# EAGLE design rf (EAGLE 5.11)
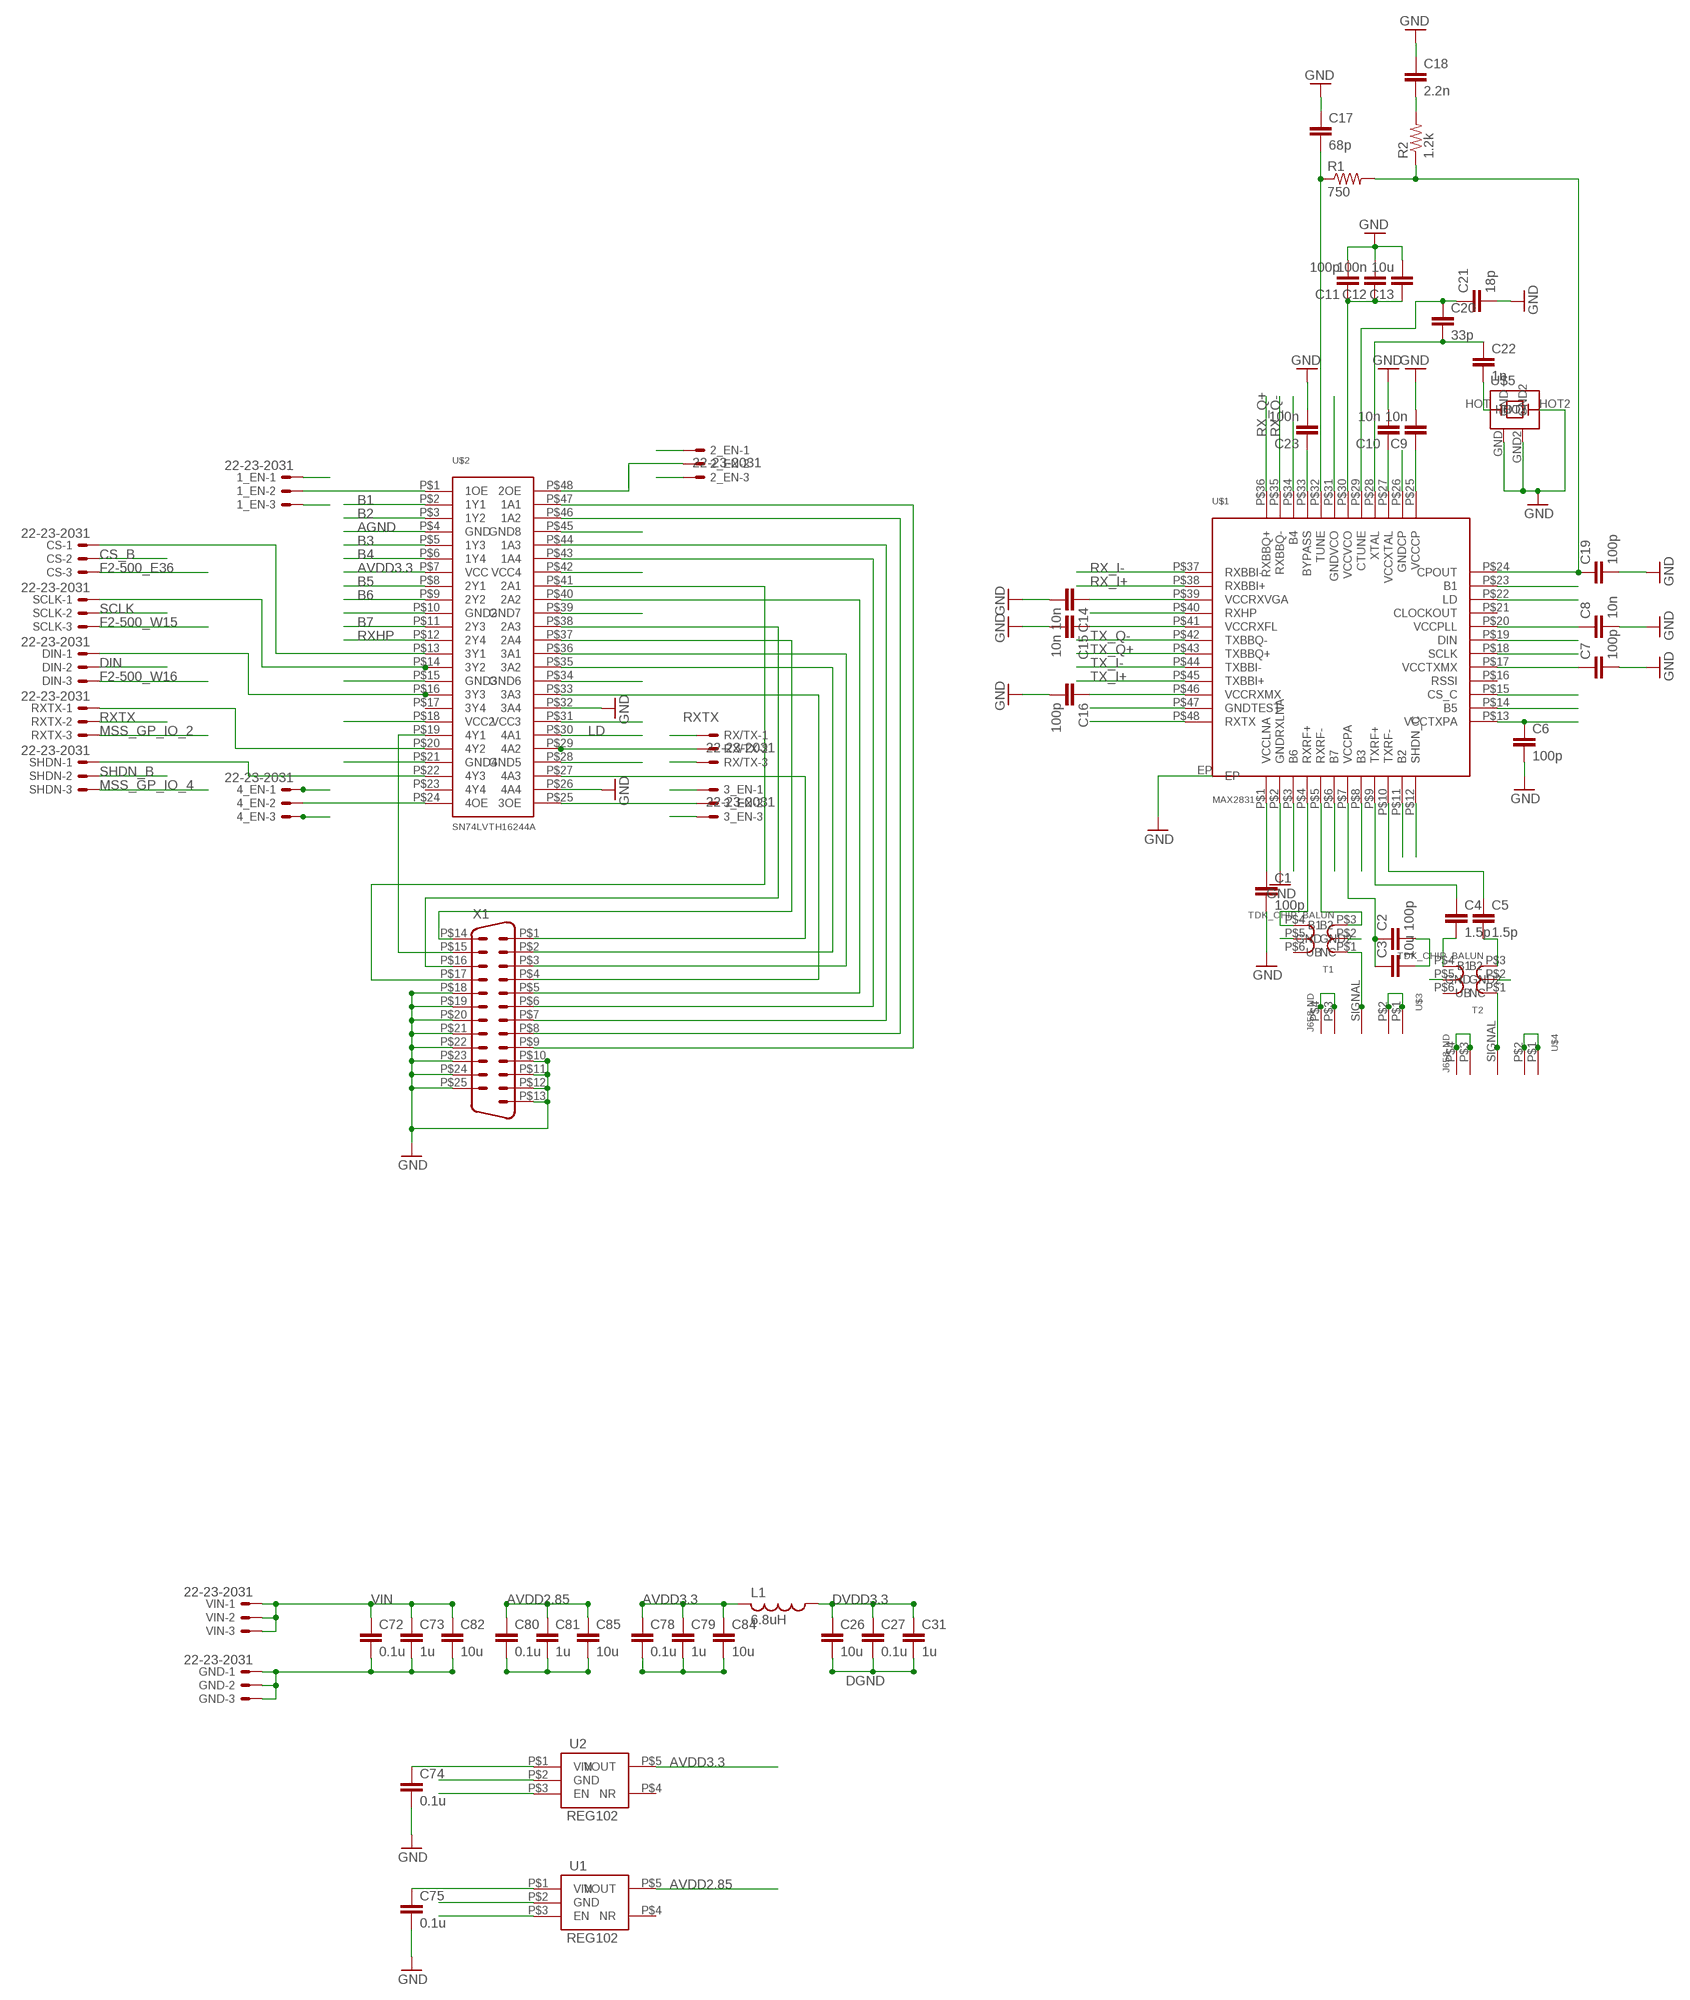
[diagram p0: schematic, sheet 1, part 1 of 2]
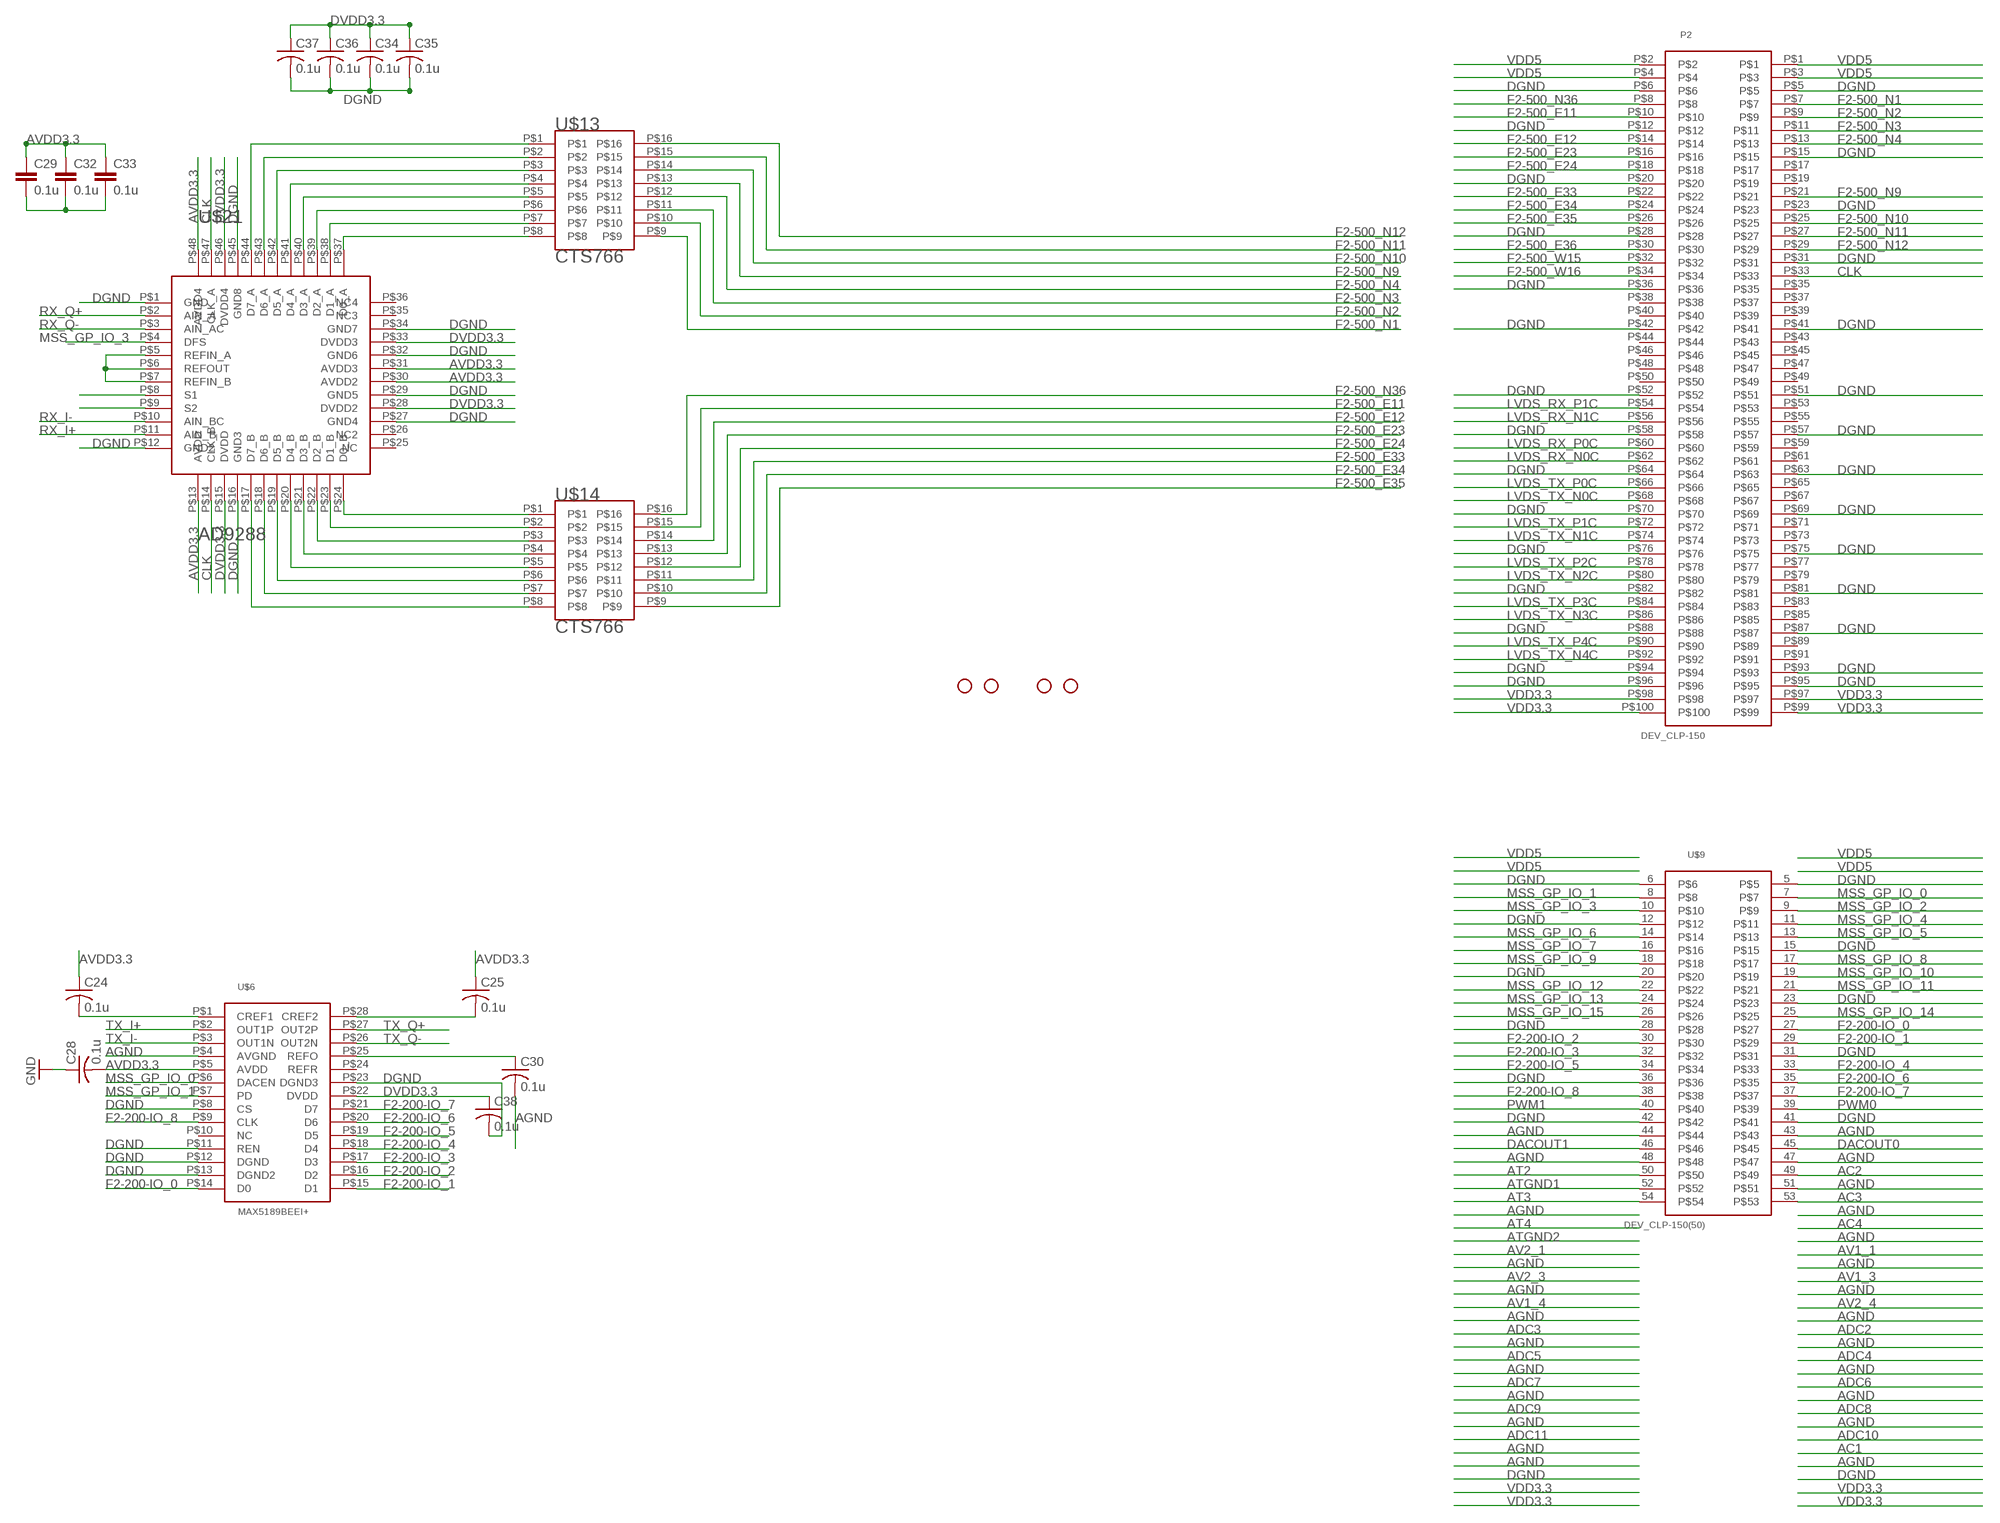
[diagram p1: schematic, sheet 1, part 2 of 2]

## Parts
1_EN  22-23-2031  [22-23-2031]
2_EN  22-23-2031  [22-23-2031]
3_EN  22-23-2031  [22-23-2031]
4_EN  22-23-2031  [22-23-2031]
C1  100p  CAP0402-CAP  [0402-CAP]
C2  100p  CAP0402-CAP  [0402-CAP]
C3  10u  CAP0805  [0805]
C4  1.5p  CAP0402-CAP  [0402-CAP]
C5  1.5p  CAP0402-CAP  [0402-CAP]
C6  100p  CAP0402-CAP  [0402-CAP]
C7  100p  CAP0402-CAP  [0402-CAP]
C8  10n  CAP0402-CAP  [0402-CAP]
C9  10n  CAP0402-CAP  [0402-CAP]
C10  10n  CAP0402-CAP  [0402-CAP]
C11  100p  CAP0402-CAP  [0402-CAP]
C12  100n  CAP0402-CAP  [0402-CAP]
C13  10u  CAP0805  [0805]
C14  10n  CAP0402-CAP  [0402-CAP]
C15  10n  CAP0402-CAP  [0402-CAP]
C16  100p  CAP0402-CAP  [0402-CAP]
C17  68p  CAP0402-CAP  [0402-CAP]
C18  2.2n  CAP0402-CAP  [0402-CAP]
C19  100p  CAP0402-CAP  [0402-CAP]
C20  33p  CAP0402-CAP  [0402-CAP]
C21  18p  CAP0402-CAP  [0402-CAP]
C22  1n  CAP0402-CAP  [0402-CAP]
C23  100n  CAP0402-CAP  [0402-CAP]
C24  0.1u  C-USC0603  [C0603]
C25  0.1u  C-USC0603  [C0603]
C26  10u  CAP0805  [0805]
C27  0.1u  CAP0603-CAP  [0603-CAP]
C28  0.1u  C-USC0603  [C0603]
C29  0.1u  CAP0603-CAP  [0603-CAP]
C30  0.1u  C-USC0603  [C0603]
C31  1u  CAP0603-CAP  [0603-CAP]
C32  0.1u  CAP0603-CAP  [0603-CAP]
C33  0.1u  CAP0603-CAP  [0603-CAP]
C34  0.1u  C-USC0603  [C0603]
C35  0.1u  C-USC0603  [C0603]
C36  0.1u  C-USC0603  [C0603]
C37  0.1u  C-USC0603  [C0603]
C38  0.1u  C-USC0603  [C0603]
C72  0.1u  CAP0603-CAP  [0603-CAP]
C73  1u  CAP0603-CAP  [0603-CAP]
C74  0.1u  CAP0603-CAP  [0603-CAP]
C75  0.1u  CAP0603-CAP  [0603-CAP]
C78  0.1u  CAP0603-CAP  [0603-CAP]
C79  1u  CAP0603-CAP  [0603-CAP]
C80  0.1u  CAP0603-CAP  [0603-CAP]
C81  1u  CAP0603-CAP  [0603-CAP]
C82  10u  CAP0805  [0805]
C84  10u  CAP0805  [0805]
C85  10u  CAP0805  [0805]
CS  22-23-2031  [22-23-2031]
DIN  22-23-2031  [22-23-2031]
GND  22-23-2031  [22-23-2031]
JP4  STAND-OFF  [STAND-OFF]
JP5  STAND-OFF  [STAND-OFF]
JP6  STAND-OFF  [STAND-OFF]
JP7  STAND-OFF  [STAND-OFF]
L1  6.8uH  L-US  [L1210]
P2  DEV_CLP-150  [CLP-150]
R1  750  RESISTOR0402-RES  [0402-RES]
R2  1.2k  RESISTOR0402-RES  [0402-RES]
RX/TX  22-23-2031  [22-23-2031]
RXTX  22-23-2031  [22-23-2031]
SCLK  22-23-2031  [22-23-2031]
SHDN  22-23-2031  [22-23-2031]
T1  TDK_CHIP_BALUN  [BALUN]
T2  TDK_CHIP_BALUN  [BALUN]
U1  REG102  [SOT-5]
U2  REG102  [SOT-5]
U$1  MAX2831  [TQFN-48]
U$2  SN74LVTH16244A  [TSSOP-48]
U$3  J658-ND  [SMA-SMD]
U$4  J658-ND  [SMA-SMD]
U$5  CX3225SB  [CX3225SB]
U$6  MAX5189BEEI+  [QSOP]
U$9  DEV_CLP-150(50)  [50PIN_HEADER]
U$13  CTS766  [SOIC-16]
U$14  CTS766  [SOIC-16]
U$21  AD9288  [LQFP(ST-48)]
VIN  22-23-2031  [22-23-2031]
X1  DB25  [DB25]

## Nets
AC2: U$9.49
AC3: U$9.53
AGND: 1_EN.1 2_EN.1 3_EN.1 4_EN.1 C1.2 C2.2 C3.2 C6.2 C7.2 C8.2 C9.2 C10.2 C11.2 C12.2 C13.2 C14.2 C15.2 C16.2 C17.1 C18.1 C19.2 C21.2 C23.2 C28.1 C30.2 C72.2 C73.2 C74.2 C75.2 C78.2 C79.2 C80.2 C81.2 C82.2 C84.2 C85.2 GND.1 GND.2 GND.3 RX/TX.1 T1.P$2(GND) T1.P$5(GND2) T2.P$2(GND) T2.P$5(GND2) U1.P$2(GND) U2.P$2(GND) U$1.EP U$1.P$2(GNDRXLNA) U$1.P$26(GNDCP) U$1.P$31(GNDVCO) U$1.P$47(GNDTEST) U$2.P$4(GND) U$2.P$10(GND2) U$2.P$15(GND3) U$2.P$21(GND4) U$2.P$26(4A4) U$2.P$28(GND5) U$2.P$32(3A4) U$2.P$34(GND6) U$2.P$39(GND7) U$2.P$45(GND8) U$3.P$1(GND1) U$3.P$2(GND2) U$3.P$3(GND3) U$3.P$4(GND4) U$4.P$1(GND1) U$4.P$2(GND2) U$4.P$3(GND3) U$4.P$4(GND4) U$5.GND U$5.GND2 U$5.HOT2 U$6.P$4(AVGND) U$9.43 U$9.44 U$9.47 U$9.48 U$9.51 X1.P$10 X1.P$11 X1.P$12 X1.P$13 X1.P$18 X1.P$19 X1.P$20 X1.P$21 X1.P$22 X1.P$23 X1.P$24 X1.P$25 ; supply symbol labelled GND
AT2: U$9.50
AT3: U$9.54
ATGND1: U$9.52
AVDD2.85: C1.1 C7.1 C8.1 C9.1 C10.1 C11.1 C12.1 C13.1 C14.1 C15.1 C16.1 C80.1 C81.1 C85.1 U1.P$5(VOUT) U$1.P$1(VCCLNA) U$1.P$17(VCCTXMX) U$1.P$20(VCCPLL) U$1.P$25(VCCCP) U$1.P$27(VCCXTAL) U$1.P$30(VCCVCO) U$1.P$39(VCCRXVGA) U$1.P$41(VCCRXFL) U$1.P$46(VCCRXMX)
AVDD3.3: 1_EN.3 2_EN.3 3_EN.3 4_EN.3 C2.1 C3.1 C6.1 C24.1 C25.1 C28.2 C29.1 C32.1 C33.1 C78.1 C79.1 C84.1 L1.2 RX/TX.3 U2.P$5(VOUT) U$1.P$7(VCCPA) U$1.P$13(VCCTXPA) U$2.P$7(VCC) U$2.P$18(VCC2) U$2.P$31(VCC3) U$2.P$42(VCC4) U$6.P$5(AVDD) U$21.P$13(AVDD) U$21.P$30(AVDD2) U$21.P$31(AVDD3) U$21.P$48(AVDD4)
B1: U$1.P$23(B1) U$2.P$2(1Y1)
B2: U$1.P$11(B2) U$2.P$3(1Y2)
B3: U$1.P$8(B3) U$2.P$5(1Y3)
B4: U$1.P$34(B4) U$2.P$6(1Y4)
B5: U$1.P$14(B5) U$2.P$8(2Y1)
B6: U$1.P$3(B6) U$2.P$9(2Y2)
B7: U$1.P$6(B7) U$2.P$11(2Y3)
CLK: P2.P$33 U$21.P$14(CLK_B) U$21.P$47(CLK_A)
CS_B: CS.2 U$1.P$15(CS_C)
DACOUT0: U$9.45
DACOUT1: U$9.46
DGND: C26.2 C27.2 C29.2 C31.2 C32.2 C33.2 C34.2 C35.2 C36.2 C37.2 C38.2 P2.P$5 P2.P$6 P2.P$12 P2.P$15 P2.P$20 P2.P$23 P2.P$28 P2.P$31 P2.P$36 P2.P$41 P2.P$42 P2.P$51 P2.P$52 P2.P$57 P2.P$58 P2.P$63 P2.P$64 P2.P$69 P2.P$70 P2.P$75 P2.P$76 P2.P$81 P2.P$82 P2.P$87 P2.P$88 P2.P$93 P2.P$94 P2.P$95 P2.P$96 U$6.P$8(CS) U$6.P$11(REN) U$6.P$12(DGND) U$6.P$13(DGND2) U$6.P$23(DGND3) U$9.5 U$9.6 U$9.12 U$9.15 U$9.20 U$9.23 U$9.28 U$9.31 U$9.36 U$9.41 U$9.42 U$21.P$1(GND) U$21.P$9(S2) U$21.P$12(GND2) U$21.P$16(GND3) U$21.P$27(GND4) U$21.P$29(GND5) U$21.P$32(GND6) U$21.P$34(GND7) U$21.P$45(GND8)
DIN: DIN.2 U$1.P$19(DIN)
DVDD3.3: C26.1 C27.1 C31.1 C34.1 C35.1 C36.1 C37.1 C38.1 L1.1 U$6.P$22(DVDD) U$21.P$8(S1) U$21.P$15(DVDD) U$21.P$28(DVDD2) U$21.P$33(DVDD3) U$21.P$46(DVDD4)
F2-200-IO_0: U$6.P$14(D0) U$9.27
F2-200-IO_1: U$6.P$15(D1) U$9.29
F2-200-IO_2: U$6.P$16(D2) U$9.30
F2-200-IO_3: U$6.P$17(D3) U$9.32
F2-200-IO_4: U$6.P$18(D4) U$9.33
F2-200-IO_5: U$6.P$19(D5) U$9.34
F2-200-IO_6: U$6.P$20(D6) U$9.35
F2-200-IO_7: U$6.P$21(D7) U$9.37
F2-200-IO_8: U$6.P$9(CLK) U$9.38
F2-500_E11: P2.P$10 U$14.P$15
F2-500_E12: P2.P$14 U$14.P$14
F2-500_E23: P2.P$16 U$14.P$13
F2-500_E24: P2.P$18 U$14.P$12
F2-500_E33: P2.P$22 U$14.P$11
F2-500_E34: P2.P$24 U$14.P$10
F2-500_E35: P2.P$26 U$14.P$9
F2-500_E36: CS.3 P2.P$30
F2-500_N1: P2.P$7 U$13.P$9
F2-500_N2: P2.P$9 U$13.P$10
F2-500_N3: P2.P$11 U$13.P$11
F2-500_N4: P2.P$13 U$13.P$12
F2-500_N9: P2.P$21 U$13.P$13
F2-500_N10: P2.P$25 U$13.P$14
F2-500_N11: P2.P$27 U$13.P$15
F2-500_N12: P2.P$29 U$13.P$16
F2-500_N36: P2.P$8 U$14.P$16
F2-500_W15: P2.P$32 SCLK.3
F2-500_W16: DIN.3 P2.P$34
LD: U$1.P$22(LD) U$2.P$30(4A1)
LVDS_RX_N0C: P2.P$62
LVDS_RX_N1C: P2.P$56
LVDS_RX_P0C: P2.P$60
LVDS_RX_P1C: P2.P$54
LVDS_TX_N0C: P2.P$68
LVDS_TX_N1C: P2.P$74
LVDS_TX_N2C: P2.P$80
LVDS_TX_N3C: P2.P$86
LVDS_TX_N4C: P2.P$92
LVDS_TX_P0C: P2.P$66
LVDS_TX_P1C: P2.P$72
LVDS_TX_P2C: P2.P$78
LVDS_TX_P3C: P2.P$84
LVDS_TX_P4C: P2.P$90
MSS_GP_IO_0: U$6.P$6(DACEN) U$9.7
MSS_GP_IO_1: U$6.P$7(PD) U$9.8
MSS_GP_IO_2: RXTX.3 U$9.9
MSS_GP_IO_3: U$9.10 U$21.P$4(DFS)
MSS_GP_IO_4: SHDN.3 U$9.11
MSS_GP_IO_5: U$9.13
MSS_GP_IO_6: U$9.14
MSS_GP_IO_7: U$9.16
MSS_GP_IO_8: U$9.17
MSS_GP_IO_9: U$9.18
MSS_GP_IO_10: U$9.19
MSS_GP_IO_11: U$9.21
MSS_GP_IO_12: U$9.22
MSS_GP_IO_13: U$9.24
MSS_GP_IO_14: U$9.25
MSS_GP_IO_15: U$9.26
N$1: 1_EN.2 U$2.P$1(1OE)
N$2: 4_EN.2 U$2.P$24(4OE)
N$3: 3_EN.2 U$2.P$25(3OE)
N$4: 2_EN.2 U$2.P$48(2OE)
N$5: T1.P$4(B2) U$1.P$4(RXRF+)
N$6: T1.P$3(B1) U$1.P$5(RXRF-)
N$7: U$2.P$27(4A3) X1.P$1
N$8: C4.1 U$1.P$9(TXRF+)
N$9: T1.P$1(UB) U$3.SIGNAL
N$10: C5.1 U$1.P$10(TXRF-)
N$11: C4.2 T2.P$4(B2)
N$12: C5.2 T2.P$3(B1)
N$13: RX/TX.2 U$2.P$29(4A2)
N$14: C17.2 R1.1 U$1.P$32(TUNE)
N$15: T2.P$1(UB) U$4.SIGNAL
N$16: C19.1 R1.2 R2.1 U$1.P$24(CPOUT)
N$17: C18.2 R2.2
N$18: C20.2 C22.1 U$1.P$28(XTAL)
N$19: C20.1 C21.1 U$1.P$29(CTUNE)
N$20: C22.2 U$5.HOT
N$21: C23.1 U$1.P$33(BYPASS)
N$22: C24.2 U$6.P$1(CREF1)
N$23: U$2.P$38(2A3) X1.P$16
N$24: C30.1 U$6.P$25(REFO)
N$25: CS.1 U$2.P$13(3Y1)
N$26: SCLK.1 U$2.P$14(3Y2)
N$27: C25.2 U$6.P$28(CREF2)
N$28: DIN.1 U$2.P$16(3Y3)
N$29: SHDN.1 U$2.P$22(4Y3)
N$30: RXTX.1 U$2.P$20(4Y2)
N$32: U$2.P$35(3A2) X1.P$2
N$33: U$2.P$36(3A1) X1.P$3
N$34: U$2.P$33(3A3) X1.P$4
N$35: U$2.P$40(2A2) X1.P$5
N$36: U$2.P$43(1A4) X1.P$6
N$37: U$2.P$44(1A3) X1.P$7
N$38: U$2.P$46(1A2) X1.P$8
N$39: U$2.P$47(1A1) X1.P$9
N$40: U$2.P$37(2A4) X1.P$14
N$41: U$2.P$19(4Y1) X1.P$15
N$42: U$21.P$5(REFIN_A) U$21.P$6(REFOUT) U$21.P$7(REFIN_B)
N$43: U$14.P$1 U$21.P$24(D0_B)
N$44: U$14.P$2 U$21.P$23(D1_B)
N$45: U$14.P$3 U$21.P$22(D2_B)
N$46: U$14.P$4 U$21.P$21(D3_B)
N$47: U$14.P$5 U$21.P$20(D4_B)
N$48: U$14.P$6 U$21.P$19(D5_B)
N$49: U$14.P$7 U$21.P$18(D6_B)
N$50: U$14.P$8 U$21.P$17(D7_B)
N$51: U$13.P$8 U$21.P$37(D0_A)
N$52: U$13.P$7 U$21.P$38(D1_A)
N$53: U$13.P$6 U$21.P$39(D2_A)
N$54: U$13.P$5 U$21.P$40(D3_A)
N$55: U$13.P$4 U$21.P$41(D4_A)
N$56: U$13.P$3 U$21.P$42(D5_A)
N$57: U$13.P$2 U$21.P$43(D6_A)
N$58: U$13.P$1 U$21.P$44(D7_A)
N$59: U$2.P$41(2A1) X1.P$17
PWM0: U$9.39
PWM1: U$9.40
RX_I+: U$1.P$38(RXBBI+) U$21.P$11(AIN_B)
RX_I-: U$1.P$37(RXBBI-) U$21.P$10(AIN_BC)
RX_Q+: U$1.P$36(RXBBQ+) U$21.P$2(AIN_A)
RX_Q-: U$1.P$35(RXBBQ-) U$21.P$3(AIN_AC)
RXHP: U$1.P$40(RXHP) U$2.P$12(2Y4)
RXTX: RXTX.2 U$1.P$48(RXTX)
SCLK: SCLK.2 U$1.P$18(SCLK)
SHDN_B: SHDN.2 U$1.P$12(SHDN_C)
TX_I+: U$1.P$45(TXBBI+) U$6.P$2(OUT1P)
TX_I-: U$1.P$44(TXBBI-) U$6.P$3(OUT1N)
TX_Q+: U$1.P$43(TXBBQ+) U$6.P$27(OUT2P)
TX_Q-: U$1.P$42(TXBBQ-) U$6.P$26(OUT2N)
VDD3.3: P2.P$97 P2.P$98 P2.P$99 P2.P$100
VDD5: P2.P$1 P2.P$2 P2.P$3 P2.P$4
VIN: C72.1 C73.1 C74.1 C75.1 C82.1 U1.P$1(VIN) U1.P$3(EN) U2.P$1(VIN) U2.P$3(EN) VIN.1 VIN.2 VIN.3
Unconnected: P2.P$17 P2.P$19 P2.P$35 P2.P$37 P2.P$38 P2.P$39 P2.P$40 P2.P$43 P2.P$44 P2.P$45 P2.P$46 P2.P$47 P2.P$48 P2.P$49 P2.P$50 P2.P$53 P2.P$55 P2.P$59 P2.P$61 P2.P$65 P2.P$67 P2.P$71 P2.P$73 P2.P$77 P2.P$79 P2.P$83 P2.P$85 P2.P$89 P2.P$91 T1.P$6(NC) T2.P$6(NC) U1.P$4(NR) U2.P$4(NR) U$1.P$16(RSSI) U$1.P$21(CLOCKOUT) U$2.P$17(3Y4) U$2.P$23(4Y4) U$6.P$10(NC) U$6.P$24(REFR) U$21.P$25(NC) U$21.P$26(NC2) U$21.P$35(NC3) U$21.P$36(NC4)

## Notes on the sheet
- RXTX

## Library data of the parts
1_EN 2_EN 3_EN 4_EN CS DIN GND RX/TX RXTX SCLK SHDN VIN = con-molex:22-23-2031: .100" (2.54mm) Center Header - 3 Pin; MF: MOLEX; MPN: 22-23-2031; OC_FARNELL: 1462950; OC_NEWARK: 30C0862
C1-C23 C26 C27 C29 C31-C33 C72-C75 C78-C82 C84 C85 = SparkFun:CAP: Capacitor
C24 C25 C28 C30 C34-C38 = rcl:C-US: CAPACITOR, American symbol
JP4-JP7 = SparkFun:STAND-OFF: Stand Off
L1 = sam:L-US: INDUCTOR, American symbol
P2 = EECS370:DEV_CLP-150
R1 R2 = SparkFun:RESISTOR: Resistor
T1 T2 = sam:TDK_CHIP_BALUN
U1 U2 = sam:REG102
U$1 = sam:MAX2831
U$2 = sam:SN74LVTH16244A
U$3 U$4 = sam:J658-ND
U$5 = sam:CX3225SB
U$6 = sam:MAX5189BEEI+
U$9 = sam:DEV_CLP-150(50)
U$13 U$14 = sam:CTS766
U$21 = sam:AD9288
X1 = sam:DB25: SUB-D

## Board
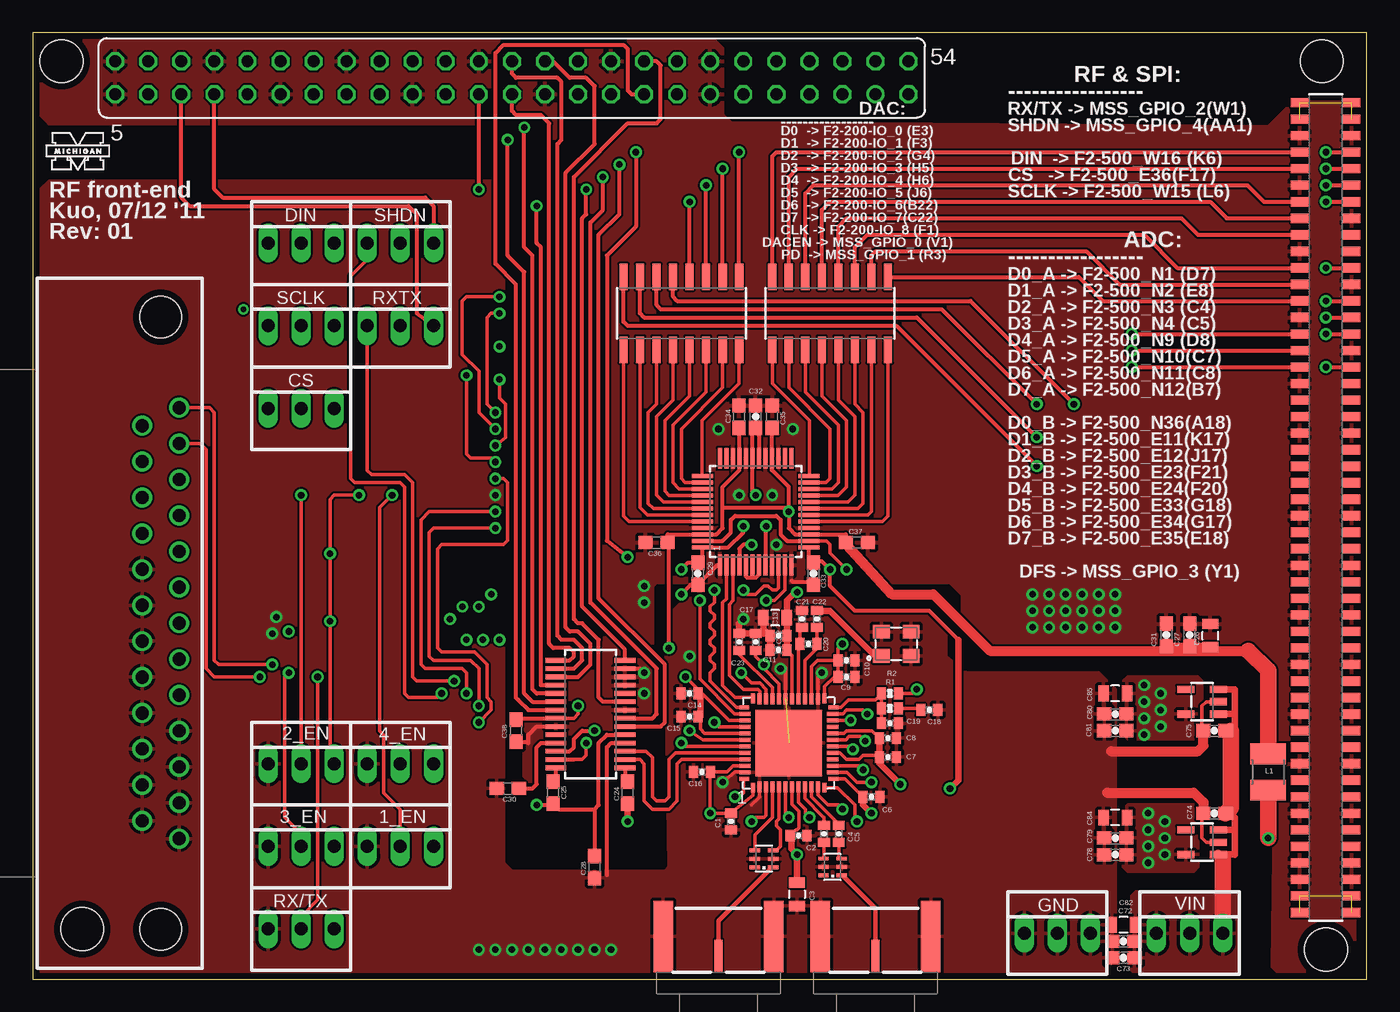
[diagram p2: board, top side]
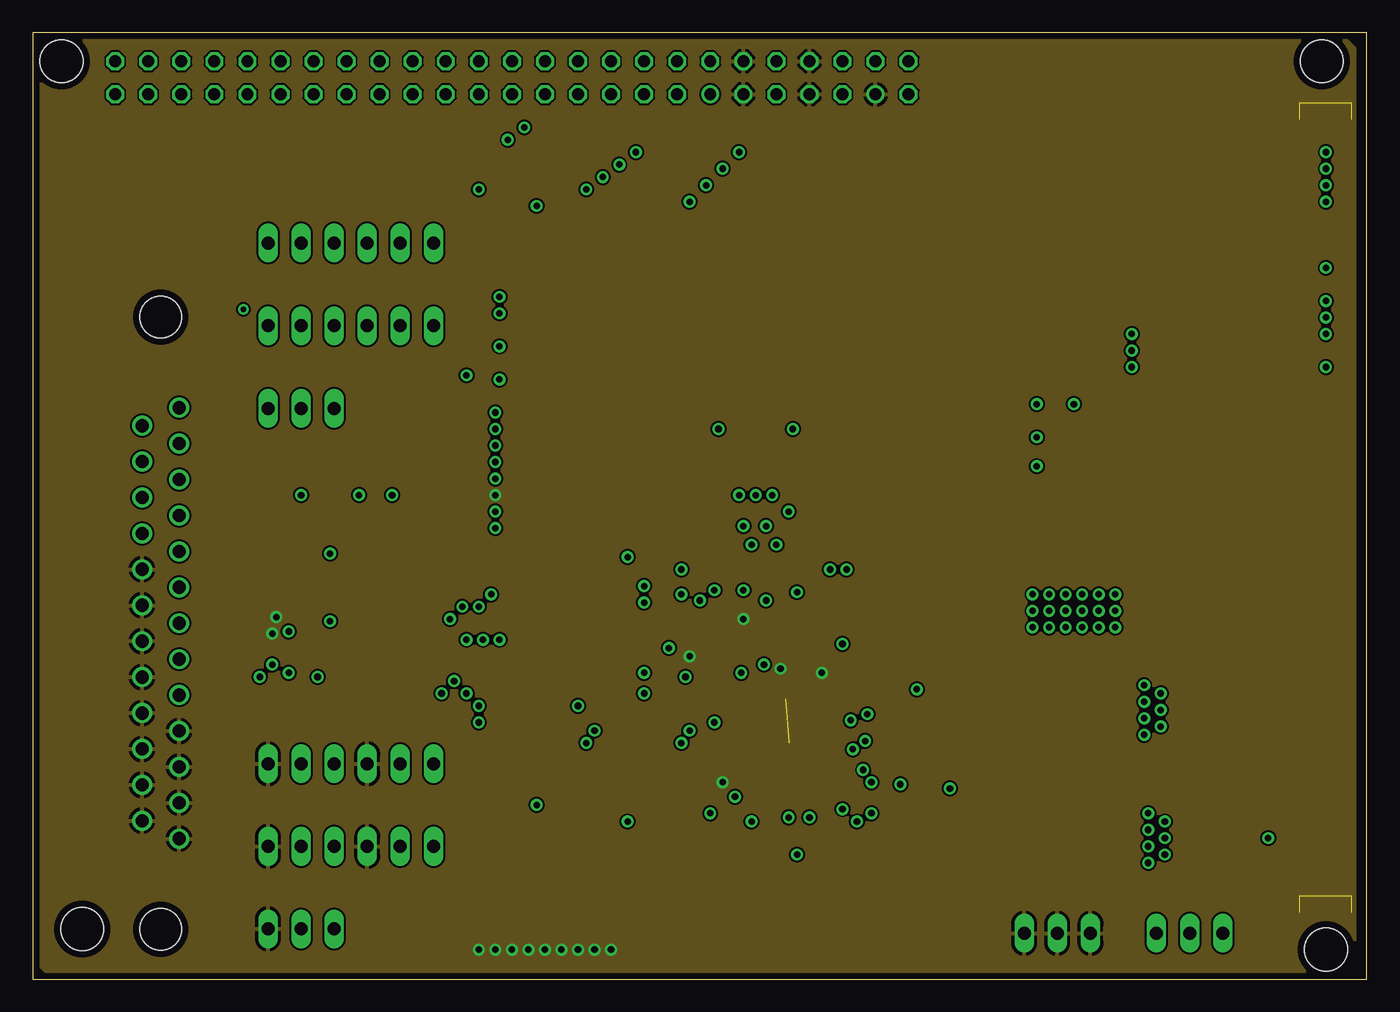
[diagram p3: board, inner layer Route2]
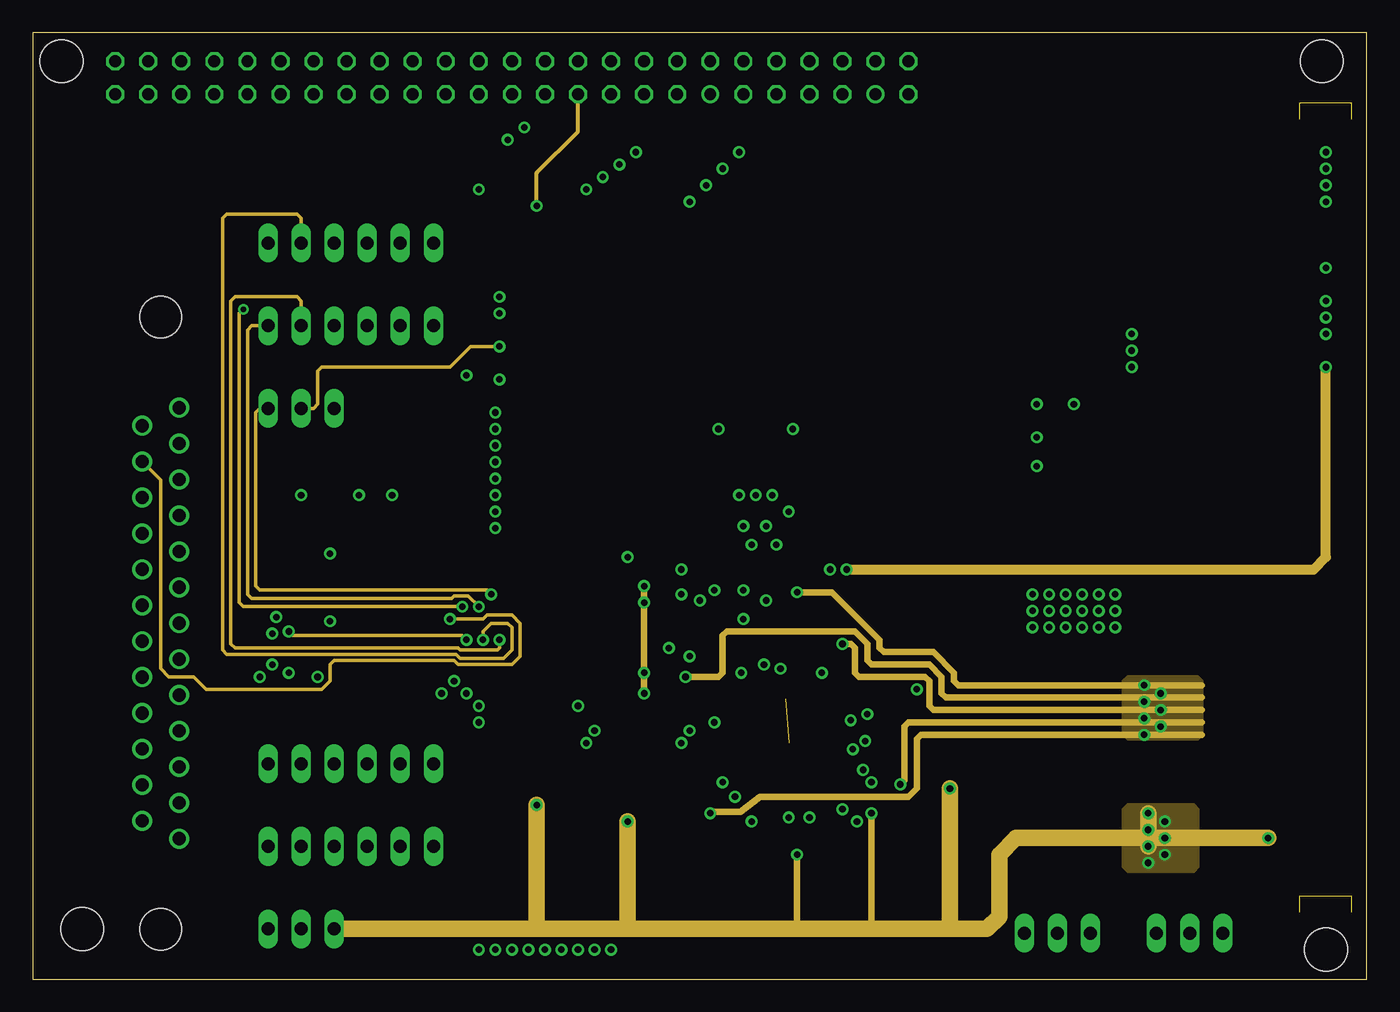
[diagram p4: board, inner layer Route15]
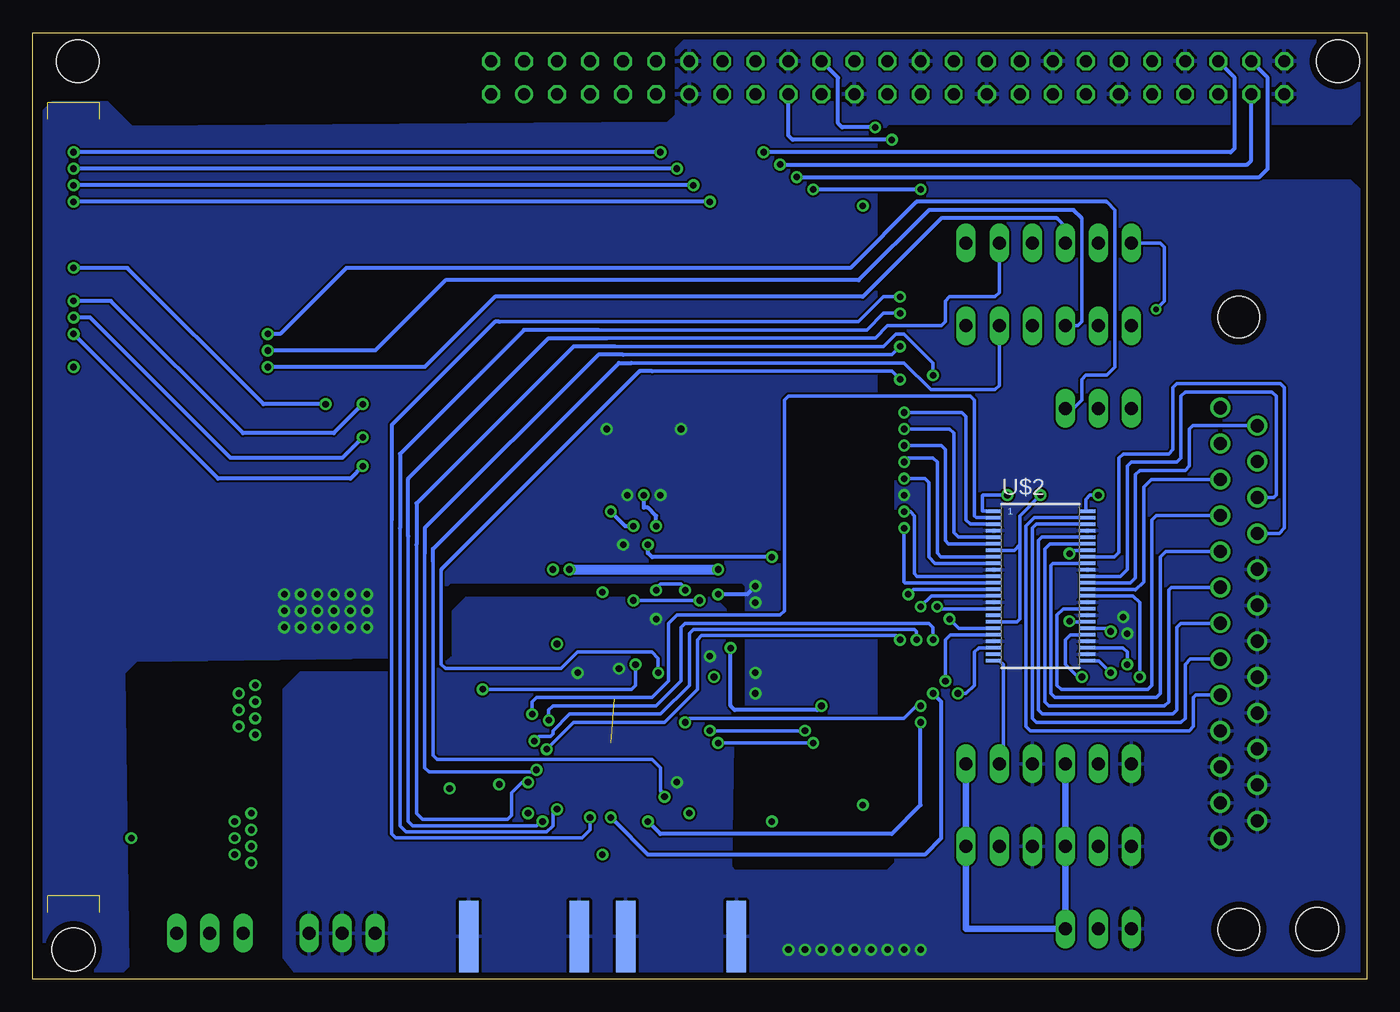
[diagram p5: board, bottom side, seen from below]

Size 102.53 x 72.73 mm. Coordinates in mm from the lower left corner, seen from the top.
Outline: 0,0 102.53,0 102.53,72.73 0,72.73 0,0
Copper layers (1+2*15+16): Top 0.0178mm / dielectric 0.3048mm / Route2 0.0356mm / dielectric 0.7112mm / Route15 0.0356mm / dielectric 0.3048mm / Bottom 0.0178mm
Design rules "SSC-EAGLE-4Lyr_v1.0.0.3 *": minimum track width 6mil, minimum drill 8mil, track to track 6mil, track to pad 6mil, pad to pad 6mil, via to via 6mil, smd to smd 6mil, copper to edge 20mil, drill to drill 16mil, minimum pad ring 8mil, minimum via ring 8mil, stop-mask expansion 3mil, vias tented up to drill 0mil, thermal gap 10mil

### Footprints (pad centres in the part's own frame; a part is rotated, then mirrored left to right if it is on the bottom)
22-23-2031 = drill 1 long: 1 -2.54,0; 2 0,0; 3 2.54,0
0402-CAP = smd 0.7 x 0.9: 1 -0.65,0; 2 0.65,0
0805 = smd 0.8 x 1.2: 1 -0.9,0; 2 0.9,0
C0603 = smd 1.1 x 1: 1 -0.85,0; 2 0.85,0
0603-CAP = smd 1.1 x 1: 1 -0.85,0; 2 0.85,0
STAND-OFF = hole 3.302: 0,0
L1210 = smd 1.6 x 2.7: 1 -1.4,0; 2 1.4,0
CLP-150 = smd 0.711 x 1.35: P$1 -31.115,1.99; P$2 -31.115,-1.99; P$3 -29.845,1.99; P$4 -29.845,-1.99; P$5 -28.575,1.99; P$6 -28.575,-1.99; P$7 -27.305,1.99; P$8 -27.305,-1.99; P$9 -26.035,1.99; P$10 -26.035,-1.99; P$11 -24.765,1.99; P$12 -24.765,-1.99; P$13 -23.495,1.99; P$14 -23.495,-1.99; P$15 -22.225,1.99; P$16 -22.225,-1.99; P$17 -20.955,1.99; P$18 -20.955,-1.99; P$19 -19.685,1.99; P$20 -19.685,-1.99; P$21 -18.415,1.99; P$22 -18.415,-1.99; P$23 -17.145,1.99; P$24 -17.145,-1.99; P$25 -15.875,1.99; P$26 -15.875,-1.99; P$27 -14.605,1.99; P$28 -14.605,-1.99; P$29 -13.335,1.99; P$30 -13.335,-1.99; P$31 -12.065,1.99; P$32 -12.065,-1.99; P$33 -10.795,1.99; P$34 -10.795,-1.99; P$35 -9.525,1.99; P$36 -9.525,-1.99; P$37 -8.255,1.99; P$38 -8.255,-1.99; P$39 -6.985,1.99; P$40 -6.985,-1.99; P$41 -5.715,1.99; P$42 -5.715,-1.99; P$43 -4.445,1.99; P$44 -4.445,-1.99; P$45 -3.175,1.99; P$46 -3.175,-1.99; P$47 -1.905,1.99; P$48 -1.905,-1.99; P$49 -0.635,1.99; P$50 -0.635,-1.99; P$51 0.635,1.99; P$52 0.635,-1.99; P$53 1.905,1.99; P$54 1.905,-1.99; P$55 3.175,1.99; P$56 3.175,-1.99; P$57 4.445,1.99; P$58 4.445,-1.99; P$59 5.715,1.99; P$60 5.715,-1.99; P$61 6.985,1.99; P$62 6.985,-1.99; P$63 8.255,1.99; P$64 8.255,-1.99; P$65 9.525,1.99; P$66 9.525,-1.99; P$67 10.795,1.99; P$68 10.795,-1.99; P$69 12.065,1.99; P$70 12.065,-1.99; P$71 13.335,1.99; P$72 13.335,-1.99; P$73 14.605,1.99; P$74 14.605,-1.99; P$75 15.875,1.99; P$76 15.875,-1.99; P$77 17.145,1.99; P$78 17.145,-1.99; P$79 18.415,1.99; P$80 18.415,-1.99; P$81 19.685,1.99; P$82 19.685,-1.99; P$83 20.955,1.99; P$84 20.955,-1.99; P$85 22.225,1.99; P$86 22.225,-1.99; P$87 23.495,1.99; P$88 23.495,-1.99; P$89 24.765,1.99; P$90 24.765,-1.99; P$91 26.035,1.99; P$92 26.035,-1.99; P$93 27.305,1.99; P$94 27.305,-1.99; P$95 28.575,1.99; P$96 28.575,-1.99; P$97 29.845,1.99; P$98 29.845,-1.99; P$99 31.115,1.99; P$100 31.115,-1.99
0402-RES = smd 0.7 x 0.9: 1 -0.65,0; 2 0.65,0
BALUN = smd 0.8 x 0.3: P$1 -0.7,0.65; P$2 -0.7,0; P$3 -0.7,-0.65; P$4 0.7,-0.65; P$5 0.7,0; P$6 0.7,0.65
SOT-5 = smd 1.3 x 0.55: P$1 -1.25,0.95; P$2 -1.25,0; P$3 -1.25,-0.95; P$4 1.25,-0.95; P$5 1.25,0.95
TQFN-48 = smd 5.1 x 5.1: EP 0,0 | smd 0.3 x 0.75: P$1 -2.75,-3.425; P$12 2.75,-3.425; P$25 2.75,3.425; P$36 -2.75,3.425 | smd 0.3 x 0.85: P$2 -2.25,-3.375; P$3 -1.75,-3.375; P$4 -1.25,-3.375; P$5 -0.75,-3.375; P$6 -0.25,-3.375; P$7 0.25,-3.375; P$8 0.75,-3.375; P$9 1.25,-3.375; P$10 1.75,-3.375; P$11 2.25,-3.375; P$26 2.25,3.375; P$27 1.75,3.375; P$28 1.25,3.375; P$29 0.75,3.375; P$30 0.25,3.375; P$31 -0.25,3.375; P$32 -0.75,3.375; P$33 -1.25,3.375; P$34 -1.75,3.375; P$35 -2.25,3.375 | smd 0.75 x 0.3: P$13 3.425,-2.75; P$24 3.425,2.75; P$37 -3.425,2.75; P$48 -3.425,-2.75 | smd 0.85 x 0.3: P$14 3.375,-2.25; P$15 3.375,-1.75; P$16 3.375,-1.25; P$17 3.375,-0.75; P$18 3.375,-0.25; P$19 3.375,0.25; P$20 3.375,0.75; P$21 3.375,1.25; P$22 3.375,1.75; P$23 3.375,2.25; P$38 -3.375,2.25; P$39 -3.375,1.75; P$40 -3.375,1.25; P$41 -3.375,0.75; P$42 -3.375,0.25; P$43 -3.375,-0.25; P$44 -3.375,-0.75; P$45 -3.375,-1.25; P$46 -3.375,-1.75; P$47 -3.375,-2.25
TSSOP-48 = smd 1.2 x 0.27: P$1 -3.6,5.75; P$2 -3.6,5.25; P$3 -3.6,4.75; P$4 -3.6,4.25; P$5 -3.6,3.75; P$6 -3.6,3.25; P$7 -3.6,2.75; P$8 -3.6,2.25; P$9 -3.6,1.75; P$10 -3.6,1.25; P$11 -3.6,0.75; P$12 -3.6,0.25; P$13 -3.6,-0.25; P$14 -3.6,-0.75; P$15 -3.6,-1.25; P$16 -3.6,-1.75; P$17 -3.6,-2.25; P$18 -3.6,-2.75; P$19 -3.6,-3.25; P$20 -3.6,-3.75; P$21 -3.6,-4.25; P$22 -3.6,-4.75; P$23 -3.6,-5.25; P$24 -3.6,-5.75; P$25 3.6,-5.75; P$26 3.6,-5.25; P$27 3.6,-4.75; P$28 3.6,-4.25; P$29 3.6,-3.75; P$30 3.6,-3.25; P$31 3.6,-2.75; P$32 3.6,-2.25; P$33 3.6,-1.75; P$34 3.6,-1.25; P$35 3.6,-0.75; P$36 3.6,-0.25; P$37 3.6,0.25; P$38 3.6,0.75; P$39 3.6,1.25; P$40 3.6,1.75; P$41 3.6,2.25; P$42 3.6,2.75; P$43 3.6,3.25; P$44 3.6,3.75; P$45 3.6,4.25; P$46 3.6,4.75; P$47 3.6,5.25; P$48 3.6,5.75
SMA-SMD = smd 1.5 x 5.5: P$1 -4.25,-0.375; P$2 4.25,-0.375 | smd 1.5 x 5.5 bottom: P$3 4.25,-0.375; P$4 -4.25,-0.375 | smd 0.6 x 2.5: SIGNAL 0,1.125
CX3225SB = smd 1.3 x 1.05: GND 1.15,-0.925; GND2 -1.15,0.925; HOT -1.15,-0.925; HOT2 1.15,0.925
QSOP = smd 1.6 x 0.356: P$1 -2.655,4.128; P$2 -2.655,3.493; P$3 -2.655,2.857; P$4 -2.655,2.223; P$5 -2.655,1.587; P$6 -2.655,0.953; P$7 -2.655,0.318; P$8 -2.655,-0.318; P$9 -2.655,-0.953; P$10 -2.655,-1.587; P$11 -2.655,-2.223; P$12 -2.655,-2.857; P$13 -2.655,-3.493; P$14 -2.655,-4.128; P$15 2.655,-4.128; P$16 2.655,-3.493; P$17 2.655,-2.857; P$18 2.655,-2.223; P$19 2.655,-1.587; P$20 2.655,-0.953; P$21 2.655,-0.318; P$22 2.655,0.318; P$23 2.655,0.953; P$24 2.655,1.587; P$25 2.655,2.223; P$26 2.655,2.857; P$27 2.655,3.493; P$28 2.655,4.128
50PIN_HEADER = drill 0.914 octagon: 5 -30.48,-1.27; 6 -30.48,1.27; 7 -27.94,-1.27; 8 -27.94,1.27; 9 -25.4,-1.27; 10 -25.4,1.27; 11 -22.86,-1.27; 12 -22.86,1.27; 13 -20.32,-1.27; 14 -20.32,1.27; 15 -17.78,-1.27; 16 -17.78,1.27; 17 -15.24,-1.27; 18 -15.24,1.27; 19 -12.7,-1.27; 20 -12.7,1.27; 21 -10.16,-1.27; 22 -10.16,1.27; 23 -7.62,-1.27; 24 -7.62,1.27; 25 -5.08,-1.27; 26 -5.08,1.27; 27 -2.54,-1.27; 28 -2.54,1.27; 29 0,-1.27; 30 0,1.27; 31 2.54,-1.27; 32 2.54,1.27; 33 5.08,-1.27; 34 5.08,1.27; 35 7.62,-1.27; 36 7.62,1.27; 37 10.16,-1.27; 38 10.16,1.27; 39 12.7,-1.27; 40 12.7,1.27; 42 15.24,1.27; 43 17.78,-1.27; 44 17.78,1.27; 45 20.32,-1.27; 46 20.32,1.27; 47 22.86,-1.27; 48 22.86,1.27; 49 25.4,-1.27; 50 25.4,1.27; 52 27.94,1.27; 53 30.48,-1.27; 54 30.48,1.27 | drill 0.914 round: 41 15.24,-1.27; 51 27.94,-1.27
SOIC-16 = smd 2.03 x 0.63: P$1 -2.8,4.445; P$2 -2.8,3.175; P$3 -2.8,1.905; P$4 -2.8,0.635; P$5 -2.8,-0.635; P$6 -2.8,-1.905; P$7 -2.8,-3.175; P$8 -2.8,-4.445; P$9 2.8,-4.445; P$10 2.8,-3.175; P$11 2.8,-1.905; P$12 2.8,-0.635; P$13 2.8,0.635; P$14 2.8,1.905; P$15 2.8,3.175; P$16 2.8,4.445
LQFP(ST-48) = smd 1.6 x 0.3: P$1 -4.1,2.75; P$2 -4.1,2.25; P$3 -4.1,1.75; P$4 -4.1,1.25; P$5 -4.1,0.75; P$6 -4.1,0.25; P$7 -4.1,-0.25; P$8 -4.1,-0.75; P$9 -4.1,-1.25; P$10 -4.1,-1.75; P$11 -4.1,-2.25; P$12 -4.1,-2.75; P$25 4.1,-2.75; P$26 4.1,-2.25; P$27 4.1,-1.75; P$28 4.1,-1.25; P$29 4.1,-0.75; P$30 4.1,-0.25; P$31 4.1,0.25; P$32 4.1,0.75; P$33 4.1,1.25; P$34 4.1,1.75; P$35 4.1,2.25; P$36 4.1,2.75 | smd 0.3 x 1.6: P$13 -2.75,-4.1; P$14 -2.25,-4.1; P$15 -1.75,-4.1; P$16 -1.25,-4.1; P$17 -0.75,-4.1; P$18 -0.25,-4.1; P$19 0.25,-4.1; P$20 0.75,-4.1; P$21 1.25,-4.1; P$22 1.75,-4.1; P$23 2.25,-4.1; P$24 2.75,-4.1; P$37 2.75,4.1; P$38 2.25,4.1; P$39 1.75,4.1; P$40 1.25,4.1; P$41 0.75,4.1; P$42 0.25,4.1; P$43 -0.25,4.1; P$44 -0.75,4.1; P$45 -1.25,4.1; P$46 -1.75,4.1; P$47 -2.25,4.1; P$48 -2.75,4.1
DB25 = drill 1.02 round: P$1 -16.56,1.42; P$2 -13.8,1.42; P$3 -11.04,1.42; P$4 -8.28,1.42; P$5 -5.52,1.42; P$6 -2.76,1.42; P$7 0,1.42; P$8 2.76,1.42; P$9 5.52,1.42; P$10 8.28,1.42; P$11 11.04,1.42; P$12 13.8,1.42; P$13 16.56,1.42; P$14 -15.18,-1.42; P$15 -12.42,-1.42; P$16 -9.66,-1.42; P$17 -6.9,-1.42; P$18 -4.14,-1.42; P$19 -1.38,-1.42; P$20 1.38,-1.42; P$21 4.14,-1.42; P$22 6.9,-1.42; P$23 9.66,-1.42; P$24 12.42,-1.42; P$25 15.18,-1.42 | hole 3.18: -23.52,0; 23.52,0

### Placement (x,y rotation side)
1_EN  28.26,10.2 0 top
2_EN  20.64,16.55 0 top
3_EN  20.64,10.2 0 top
4_EN  28.26,16.55 0 top
C1  53.66,12.1 270 top
C2  58.86,11.02 0 top
C3  58.74,6.52 270 top
C4  60.8,11.15 270 top
C5  61.94,11.15 270 top
C6  64.45,14.01 0 top
C7  65.72,17.06 0 top
C8  65.72,18.52 0 top
C9  62.55,23.22 0 top
C10  62.55,24.49 0 top
C11  57.31,25.28 180 top
C12  57.31,26.39 180 top
C13  57.05,27.76 180 top
C14  50.48,21.95 180 top
C15  50.48,20.17 180 top
C16  51.44,15.91 180 top
C17  55.56,25.91 270 top
C18  68.9,20.68 180 top
C19  65.88,19.66 0 top
C20  59.63,25.76 0 top
C21  59.12,27.66 90 top
C22  60.26,27.66 90 top
C23  54.29,25.91 90 top
C24  45.72,14.33 90 top
C25  40.01,14.33 90 top
C26  90.49,26.39 90 top
C27  88.9,26.45 90 top
C28  43.18,8.61 90 top
C29  51.12,31.15 270 top
C30  36.51,14.64 180 top
C31  87.12,26.45 90 top
C32  55.56,43.22 90 top
C33  60.01,31.15 270 top
C34  54.29,43.22 90 top
C35  56.83,43.22 90 top
C36  47.94,33.53 180 top
C37  63.34,33.53 0 top
C38  37.15,19.09 270 top
C72  83.82,2.9 180 top
C73  83.82,1.63 180 top
C74  90.81,12.74 180 top
C75  90.81,19.09 180 top
C78  83.19,9.56 180 top
C79  83.19,10.83 180 top
C80  83.19,20.36 180 top
C81  83.19,19.09 180 top
C82  83.82,4.17 180 top
C84  83.19,12.42 180 top
C85  83.19,21.95 180 top
CS  20.64,43.85 0 top
DIN  20.64,56.55 0 top
GND  78.74,3.53 0 top
JP4  2.22,70.52 0 top
JP5  3.81,3.85 0 top
JP6  99.06,70.52 0 top
JP7  99.38,2.26 0 top
L1  94.93,15.91 270 top
P2  99.35,36.23 270 top
R1  65.88,21.95 180 top
R2  65.88,20.8 0 top
RX/TX  20.64,3.85 0 top
RXTX  28.26,50.2 0 top
SCLK  20.64,50.2 0 top
SHDN  28.26,56.55 0 top
T1  56.2,9.25 180 top
T2  61.47,8.61 180 top
U1  89.85,21.31 180 top
U2  89.85,10.52 180 top
U$1  58.1,18.14 0 top
U$2  25.08,30.2 0 bottom
U$3  52.7,2.9 180 top
U$4  64.77,2.9 180 top
U$5  66.36,25.76 0 top
U$6  42.86,20.36 180 top
U$8  [UMICH]  0.95,61.95 0 top
U$9  36.83,69.25 0 top
U$13  49.85,51.16 90 top
U$14  61.28,51.16 90 top
U$21  55.56,35.92 90 top
VIN  88.9,3.53 0 top
X1  9.84,27.34 270 top

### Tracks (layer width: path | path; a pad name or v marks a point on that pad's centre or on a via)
AGND  (via drill 0.51)  (1 unrouted)
  Top 0.254: v53.02,15.12 53.98,15.91 54.7,15.91 U$1.P$47 | U$1.P$26 60.35,23.24 v60.64,23.53 | C11.2 56.66,24.98 56.82,24.98 | U$1.P$31 57.85,23.94 | U$1.P$2 55.85,13.98 55.24,13.37 | U2.P$2 90.17,10.52 89.85,10.83 89.85,12.64 C74.2 | U1.P$2 90.17,21.31 89.85,20.99 89.85,19.19 C75.2
  Top 0.305: U$6.P$4 44.45,18.14 44.13,17.82 44.13,7.98
  Top 0.508: C12.2 C11.2 | C11.2 | C12.2 56.48,26.56 C17.1 C23.2 54.29,27.34 v54.61,27.66 | C13.2 56.16,26.89 C12.2
  Top 0.762: C74.2 89.95,13.59 89.22,14.33 82.55,14.33 | C75.2 89.95,17.92 89.53,17.5 82.87,17.5
  other vias: 57.47,23.85 34.29,2.26 35.56,2.26 36.83,2.26 38.1,2.26 39.37,2.26 40.64,2.26 41.91,2.26 43.18,2.26 44.45,2.26 18.73,27.82 50.48,24.8 18.41,26.55 35.56,37.19
  pour Top: 48.58,27.66 48.9,8.61 48.58,8.29 36.83,8.29 36.2,8.93 36.2,60.68 35.56,61.32 1.27,61.32 0.64,60.68 0.32,0.36 0.64,0.04 81.92,0.04 83.19,1.63 83.19,22.26 81.92,23.53 71.75,23.53 70.17,24.8 70.17,28.3 69.22,29.25 50.16,29.25
  pour Route2: 1.59,72.11 0.32,70.52 0.32,1.31 1.59,0.04 100.65,0.36 101.6,1.31 101.6,71.48 100.97,72.11
  pour Bottom: 48.58,27.66 48.9,8.61 48.58,8.29 36.83,8.29 36.2,8.93 36.2,60.68 35.56,61.32 1.27,61.32 0.64,60.68 0.32,0.36 0.64,0.04 81.92,0.04 83.19,1.63 83.19,22.26 81.92,23.53 71.75,23.53 70.17,24.8 70.17,28.3 69.22,29.25 50.16,29.25
AVDD2.85  (via drill 0.51)
  Top 0.254: U$1.P$46 53.81,16.39 53.34,15.91 C16.1 52.07,15.9 v52.07,12.74 53.96,12.74 C1.1 55.35,14.13 U$1.P$1 | U$1.P$17 62.03,17.39 62.55,16.87 63.5,16.87 63.82,17.18 64.94,17.18 C7.1 | U$1.P$30 58.35,24.89 C11.1 | C10.1 C9.1 61.59,23.22 60.85,22.47 U$1.P$25 | C10.1 61.9,25.42 v62.23,25.76 | U$1.P$27 59.85,24.01 60.33,24.49 C10.1 | v50.16,23.22 51.13,22.25 C14.1 51.44,21.95 53.49,19.89 U$1.P$39 | C15.1 51.31,20.17 51.31,19.21 51.64,18.89 U$1.P$41 | U$1.P$20 62.34,18.89 62.55,19.09 64.5,19.09 C8.1 65.02,18.52
  Top 0.508: C12.1 | 57.96,27.59 C13.1 57.96,27.59 | C12.1 57.96,27.59 | C11.1 C12.1 | 57.96,27.59 57.96,29.1 58.58,29.72 v58.74,29.72 | 51.31,20.17 51.31,21.77 C14.1 | v66.67,14.96 65.07,16.56 C7.1 C8.1
  Route15 0.508: 89.85,19.72 67.31,19.72 66.99,19.41 66.99,15.28 v66.67,14.96 | 89.85,18.77 68.26,18.77 67.94,18.45 67.94,14.64 67.31,14.01 55.88,14.01 54.4,12.85 52.18,12.85 v52.07,12.74 | v62.23,25.76 62.87,25.76 63.18,25.44 63.18,23.53 63.5,23.22 68.58,23.22 68.9,22.9 68.9,20.99 69.22,20.68 89.85,20.68 | 89.85,21.63 70.17,21.63 69.85,21.95 69.85,23.22 68.9,24.17 64.45,24.17 64.14,24.49 64.14,25.76 63.18,26.71 53.34,26.71 53.02,26.39 53.02,23.53 52.7,23.22 v50.16,23.22 | v58.74,29.72 61.44,29.72 65.09,26.07 65.09,25.44 65.41,25.12 69.22,25.12 70.8,23.53 70.8,22.9 71.12,22.58 v85.41,22.58 89.85,22.58
  other vias: 85.41,21.31 85.41,20.04 85.41,18.77 86.68,19.41 86.68,20.68 86.68,21.95
  pour Top: 84.14,23.22 83.82,22.9 83.82,18.77 84.14,18.45 89.53,18.45 89.85,18.77 89.85,22.9 89.53,23.22
  pour Route15: 84.14,23.22 83.82,22.9 83.82,18.77 84.14,18.45 89.53,18.45 89.85,18.77 89.85,22.9 89.53,23.22
AVDD3.3  (via drill 0.51)
  Top 0.254: 58.29,11.02 C2.1 58.66,11.47 58.74,11.47 58.9,11.63 58.9,12.9 58.35,13.44 U$1.P$7 | U$1.P$13 62.42,15.39 C6.1 | 2_EN.3 22.86,16.87 v22.86,27.5 v22.86,32.69 22.86,36.87 23.18,37.19 v25.08,37.19
  Top 0.305: U$6.P$5 44.13,18.77 43.5,18.14 43.5,13.37 43.18,13.06 | 43.5,9.78 C28.2 43.18,13.06 | v38.73,13.37 39.9,13.37 C25.1 40.42,13.06 43.18,13.06 | U$21.P$30 55.81,41.8 C32.1 55.31,41.8 U$21.P$31 55.31,37.44 v55.56,37.19 | U$21.P$13 59.66,32.35 C33.1 60.22,32.11 60.64,32.11 v61.28,31.47 61.28,30.2 63.18,28.3 68.9,28.3 71.12,26.07 | v49.85,31.47 50.38,32 C29.1 51.46,32.35 U$21.P$48 53.45,33.17 54.61,34.33 v54.61,34.8
  Top 0.508: 58.29,11.02 58.29,10.01 v58.74,9.56 C3.1 | C6.1 63.8,13.39 v64.45,12.74 | v70.48,14.64 71.12,15.28 71.12,26.07 | v45.72,12.1 C24.1
  Top 1.27: v94.93,10.83 L1.2
  Route15 0.508: 58.74,3.85 v58.74,9.56 | 64.45,3.85 v64.45,12.74
  Route15 1.27: RX/TX.3 38.73,3.85 | 38.73,3.85 45.72,3.85 | 45.72,3.85 58.74,3.85 64.45,3.85 70.48,3.85 | 70.48,3.85 73.34,3.85 74.3,4.8 74.3,9.56 75.56,10.83 85.72,10.83 | 45.72,3.85 v45.72,12.1 | 38.73,3.85 v38.73,13.37 | 85.72,10.83 v85.72,10.2 | 85.72,10.83 v85.72,11.47 v85.72,12.74 | 70.48,3.85 v70.48,14.64 | 85.72,10.83 v87,10.83 v94.93,10.83
  Bottom 0.254: U$2.P$42 22.65,32.95 v22.86,32.69 | U$2.P$31 22.75,27.45 v22.86,27.5 | v25.08,37.19 26.67,35.6 26.67,33.38 | U$2.P$7 27.09,32.95 26.67,33.38 | 26.67,33.38 26.67,27.66 26.88,27.45 U$2.P$18
  Bottom 0.305: v55.56,37.19 55.56,36.23 55.24,36.23 54.61,35.6 v54.61,34.8
  Bottom 0.508: 4_EN.3 1_EN.3 30.8,3.85 RX/TX.3 3_EN.3 2_EN.3
  Bottom 0.762: v61.28,31.47 v49.85,31.47
  other vias: 85.72,8.93 87,9.56 87,12.1
  pour Top: 84.14,13.37 83.82,13.06 83.82,8.61 84.14,8.29 89.22,8.29 89.53,8.61 89.53,13.06 89.22,13.37
  pour Route15: 84.14,13.37 83.82,13.06 83.82,8.61 84.14,8.29 89.22,8.29 89.53,8.61 89.53,13.06 89.22,13.37
B1  (via drill 0.51)
  Top 0.254: U$1.P$23 62.26,20.39 62.55,20.68 63.82,20.68 v64.14,20.36
  Bottom 0.254: U$2.P$2 30.02,35.45 30.16,35.6 30.16,44.49 30.48,44.81 44.45,44.81 44.77,44.49 44.77,28.3 45.09,27.98 53.02,27.98 53.66,27.34 53.66,22.9 54.93,21.63 63.82,21.63 64.14,21.31 v64.14,20.36
B2  (via drill 0.51)
  Top 0.254: v35.56,43.54 34.92,44.17 34.92,50.84 35.24,51.16 v35.88,51.16 | U$1.P$11 60.35,14.14 61.12,13.37 61.91,13.37 v62.23,13.06
  Bottom 0.254: U$2.P$3 30.47,34.95 30.8,35.28 30.8,43.22 31.11,43.54 v35.56,43.54 | 74.3,34.65 74.3,11.79 73.82,11.31 63.02,11.31 62.55,11.79 62.55,12.74 v62.23,13.06 | 59.05,49.89 38.42,49.89 37.15,51.16 v35.88,51.16
  Bottom 0.305: 59.05,49.89 64.77,49.89 74.3,40.36 74.3,34.65
B3  (via drill 0.51)
  Top 0.254: v35.56,42.27 34.29,43.54 34.29,46.71 33.02,47.98 33.02,52.11 33.34,52.43 v35.88,52.43 | U$1.P$8 58.85,13.58 59.37,13.06 59.37,12.74 v59.69,12.42
  Bottom 0.254: U$2.P$5 31.37,33.95 31.75,34.33 31.75,41.95 32.07,42.27 v35.56,42.27 | v59.69,12.42 59.69,11.47 60.33,10.83 74.61,10.83 74.93,11.15 74.93,35.28 | 66.67,50.52 39.05,50.52 37.15,52.43 v35.88,52.43
  Bottom 0.305: 66.67,50.52 66.99,50.52 74.93,42.58 74.93,35.28
B4  (via drill 0.51)
  Top 0.254: U$1.P$34 56.35,22.27 55.88,22.74 55.24,22.74 v54.45,23.53 | v35.88,46.08 35.88,44.65 36.35,44.17 36.35,41.63 v35.56,41
  Bottom 0.254: U$2.P$6 32.14,33.45 32.38,33.69 32.38,40.68 32.7,41 v35.56,41 | v54.45,23.53 54.45,24.64 54.93,25.12 60.64,25.12 61.91,23.85 70.8,23.85 71.12,24.17 71.12,31.47 | 54.93,46.71 36.51,46.71 v35.88,46.08
  Bottom 0.305: 54.93,46.71 55.88,46.71 71.12,31.47
B5  (via drill 0.51)
  Top 0.254: U$1.P$14 62.58,15.89 63.34,15.12 v64.45,15.12 | v33.34,46.39 33.34,40.36 33.66,40.04 35.24,40.04 v35.56,39.73
  Bottom 0.254: U$2.P$8 32.73,32.45 33.02,32.74 33.02,39.73 33.34,40.04 35.24,40.04 v35.56,39.73 | v64.45,15.12 64.93,15.12 65.72,14.33 65.72,12.58 66.04,12.26 72.55,12.26 73.03,12.74 73.03,33.38 | 57.78,48.62 37.15,48.62 36.2,49.57 35.56,49.57 33.34,47.35 v33.34,46.39
  Bottom 0.305: 57.78,48.62 60.96,48.62 73.03,36.55 73.03,33.38
B6  (via drill 0.51)
  Top 0.254: v34.29,19.72 35.24,20.68 35.24,21.31 34.92,21.63 34.92,24.17 33.97,25.12 31.43,25.12 31.11,25.44 31.11,33.06 31.43,33.38 36.2,33.38 36.51,33.69 36.51,38.14 36.2,38.46 v35.56,38.46 | U$1.P$3 56.35,12.58 56.2,12.42 55.56,12.42 v55.24,12.1
  Bottom 0.254: U$2.P$9 33.18,31.95 33.66,32.42 33.66,38.14 33.97,38.46 v35.56,38.46
  Bottom 0.305: v34.29,19.72 34.29,13.37 36.51,11.15 54.29,11.15 v55.24,12.1
B7  (via drill 0.51)
  Top 0.254: U$1.P$6 57.85,12.67 v58.1,12.42 | v33.34,21.95 33.34,23.53 33.02,23.85 30.16,23.85 29.84,24.17 29.84,35.28 30.48,35.92 v35.56,35.92
  Bottom 0.254: U$2.P$11 34.56,30.95 34.77,31.15 34.77,35.6 35.08,35.92 v35.56,35.92 | 57.78,12.1 v58.1,12.42
  Bottom 0.305: 57.78,12.1 55.24,9.56 33.97,9.56 32.7,10.83 32.7,21.31 v33.34,21.95
CLK  (via drill 0.51)
  Top 0.254: U$21.P$14 60.99,33.67 61.28,33.38 61.28,32.74 v62.55,31.47
  Top 0.305: U$21.P$47 52.99,33.67 53.66,34.33 53.66,35.28 53.98,35.6 57.15,35.6 57.47,35.28 57.47,34.17 57.97,33.67 U$21.P$14 | v99.38,47.03 P2.P$33
  Route15 0.762: v62.55,31.47 98.42,31.47 99.38,32.42 v99.38,47.03
CS_B  (via drill 0.51)
  Top 0.254: U$1.P$15 63.5,16.39 v63.82,16.07
  Route15 0.254: CS.2 21.59,43.85 21.91,44.17 21.91,46.71 22.23,47.03 32.07,47.03 33.66,48.62 v35.88,48.62
  Bottom 0.254: v63.82,16.07 63.98,15.91 72.07,15.91 72.39,16.23 72.39,32.74 | 57.15,47.98 36.51,47.98 v35.88,48.62
  Bottom 0.305: 57.15,47.98 59.05,47.98 72.39,34.65 72.39,32.74
DGND  (via drill 0.51)
  Top 0.254: 58.42,30.52 59.79,30.52
  Top 0.305: C38.2 38,18.24 38.1,18.14 38.1,18.77 38.73,19.41 U$6.P$23 | U$6.P$13 46.67,23.85 | 58.31,30.63 58.42,30.52 | 59.79,30.52 C33.2 | v49.85,29.57 50.59,30.3 C29.2 52.63,31.82 U$21.P$1
  Route15 0.508: v46.99,21.95 v46.99,28.93 v46.99,30.2
  Bottom 0.305: v49.85,29.57 47.62,29.57 v46.99,30.2
  other vias: 57.15,33.38 54.29,37.19 56.83,37.19 46.99,23.53 52.7,42.27 58.42,42.27 76.83,29.57 78.11,29.57 79.38,29.57 80.64,29.57 81.92,29.57 83.19,29.57 76.83,28.3 78.11,28.3 79.38,28.3 80.64,28.3 81.92,28.3 83.19,28.3 76.83,27.03 78.11,27.03 79.38,27.03 80.64,27.03 81.92,27.03 83.19,27.03
  pour Top: 37.78,15.6 38.42,14.96 47.31,14.96 47.62,15.28 47.62,30.2 47.94,30.52 70.48,30.52 71.44,29.57 71.44,25.76 72.39,24.8 94.61,24.49 95.57,23.53 95.25,0.99 96.2,0.04 100.65,0.04 101.6,0.99 101.6,66.71 100.97,67.35 96.84,67.35 94.93,65.44 53.66,65.76 53.02,66.4 53.02,71.48 52.39,72.11 0.95,72.11 0.32,71.48 0.32,66.71 1.27,65.76 36.83,65.76 37.78,64.49
  pour Top: 37.78,15.6 38.42,14.96 47.31,14.96 47.62,15.28 47.62,30.2 47.94,30.52 70.48,30.52 71.44,29.57 71.44,25.76 72.39,24.8 94.61,24.49 95.57,23.53 95.25,0.99 96.2,0.04 100.65,0.04 101.6,0.99 101.6,66.71 100.97,67.35 96.84,67.35 94.93,65.44 53.66,65.76 53.02,66.4 53.02,71.48 52.39,72.11 0.95,72.11 0.32,71.48 0.32,66.71 1.27,65.76 36.83,65.76 37.78,64.49
  pour Bottom: 37.78,15.6 38.42,14.96 47.31,14.96 47.62,15.28 47.62,30.2 47.94,30.52 70.48,30.52 71.44,29.57 71.44,25.76 72.39,24.8 94.61,24.49 95.57,23.53 95.25,0.99 96.2,0.04 100.65,0.04 101.6,0.99 101.6,66.71 100.97,67.35 96.84,67.35 94.93,65.44 53.66,65.76 53.02,66.4 53.02,71.48 52.39,72.11 0.95,72.11 0.32,71.48 0.32,66.71 1.27,65.76 36.83,65.76 37.78,64.49
DIN  (via drill 0.51)
  Top 0.254: U$1.P$19 62.48,18.39 62.74,18.64 63.63,18.64 v63.98,18.29
  Route15 0.254: DIN.2 20.64,58.46 20.32,58.78 14.92,58.78 14.61,58.46 14.61,25.28 14.92,24.96 32.54,24.96 32.86,24.64 36.2,24.64 36.83,25.28 36.83,27.03 36.51,27.34 35.24,27.34 34.61,26.71 v34.61,26.07
  Bottom 0.254: v34.61,26.07 34.61,26.71 34.77,26.87 51.75,26.87 52.07,26.55 52.07,22.58 54.29,20.36 61.28,20.36 62.55,19.09 62.55,18.83 62.74,18.64 63.63,18.64 v63.98,18.29
DVDD3.3  (via drill 0.51)
  Top 0.254: U$6.P$22 41.59,20.04 41.91,20.36 v41.91,20.99
  Top 0.305: C35.1 56.81,42.03 U$21.P$28 56.81,39.11 58.1,37.82 58.1,36.23 | C34.1 54.31,42.03 U$21.P$33 54.31,39.11 53.02,37.82 53.02,36.23 | 53.02,36.23 58.1,36.23 | 58.1,36.23 v58.1,35.92 58.1,34.65 58.58,34.17 U$21.P$15 62.49,34.17 C37.1 | 53.02,36.23 53.02,34.65 52.54,34.17 U$21.P$46 48.8,34.17 C36.1 48.9,34.07 v48.9,25.44 | U$6.P$22 37.25,20.04 C38.1 | U$21.P$8 56.31,34.76 v56.36,34.8
  Top 0.508: C31.1 C27.1 90.37,25.6 C26.1
  Top 0.762: C37.1 62.49,33.43 62.55,33.38 66.04,29.57 69.22,29.57 73.56,25.22 90.75,25.22 | 90.75,25.22 93.41,25.22 | 90.75,25.22 C26.1
  Top 1.27: L1.1 94.93,23.7 93.41,25.22
  Bottom 0.305: v41.91,20.99 42.23,20.68 48.58,20.68 48.9,20.99 v48.9,25.44 | v56.36,34.8 56.99,34.8 v58.1,35.92
F2-200-IO_0  (via drill 0.51)
  Top 0.305: U$6.P$14 45.52,25.32 42.23,28.61 42.23,58.46 42.55,58.78 v42.55,60.68 | v34.29,60.68 U$9.27
  Bottom 0.305: v42.55,60.68 v34.29,60.68
F2-200-IO_1
  Top 0.305: U$6.P$15 41.27,24.49 41.59,24.8 41.59,25.12 41.27,25.44 40.01,25.44 39.69,25.76 39.69,65.76 39.05,66.4 37.15,66.4 36.83,66.71 U$9.29
F2-200-IO_2
  Top 0.305: U$6.P$16 41.59,23.85 42.23,24.49 42.23,25.44 41.59,26.07 40.64,26.07 40.32,26.39 40.32,64.17 40.64,64.49 40.64,68.94 40.32,69.25 37.15,69.25 36.83,69.57 U$9.30
F2-200-IO_3
  Top 0.305: U$6.P$17 41.91,23.22 42.86,24.17 42.86,25.76 41.91,26.71 41.27,26.71 40.96,27.03 40.96,61.95 43.18,64.17 43.18,68.62 42.55,69.25 41.27,69.25 40.01,70.52 U$9.32
F2-200-IO_4  (via drill 0.51)
  Top 0.305: U$6.P$18 39.05,22.58 39.05,56.24 38.73,56.55 v38.73,59.41
  Route15 0.305: v38.73,59.41 38.73,61.95 41.91,65.13 U$9.33
F2-200-IO_5  (via drill 0.51)
  Top 0.305: U$6.P$19 38.73,21.95 38.42,22.26 38.42,55.6 37.78,56.24 v37.78,65.44
  Bottom 0.305: v37.78,65.44 40.32,65.44 40.64,65.76 40.64,69.25 U$9.34
F2-200-IO_6  (via drill 0.51)
  Top 0.305: U$6.P$20 38.42,21.31 37.78,21.95 37.78,54.33 36.51,55.6 v36.51,64.49
  Bottom 0.305: v36.51,64.49 44.13,64.49 44.45,64.81 U$9.35
F2-200-IO_7
  Top 0.305: U$6.P$21 38.1,20.68 37.31,21.47 37.15,21.63 37.15,53.38 35.56,54.97 35.56,71.16 36.2,71.79 45.4,71.79 45.72,71.48 45.72,68.3 46.04,67.98 U$9.37
F2-200-IO_8
  Top 0.305: U$6.P$9 43.81,21.31 43.5,21.63 43.5,26.07 42.23,27.34 41.91,27.34 41.59,27.66 41.59,61.63 45.72,65.76 47.94,65.76 48.26,66.08 48.26,70.21 47.94,70.52 U$9.38
F2-500_E11
  Top 0.305: U$14.P$15 58.1,61.63 58.74,62.27 P2.P$10
F2-500_E12
  Top 0.305: U$14.P$14 59.37,60.36 60.01,61 93.34,61 94.61,59.73 P2.P$14
F2-500_E23
  Top 0.305: U$14.P$13 60.64,59.09 61.28,59.73 90.49,59.73 91.76,58.46 P2.P$16
F2-500_E24
  Top 0.305: U$14.P$12 61.91,57.82 62.55,58.46 88.27,58.46 89.53,57.19 P2.P$18
F2-500_E33
  Top 0.305: U$14.P$11 63.18,56.24 64.14,57.19 85.41,57.19 87.95,54.65 P2.P$22
F2-500_E34
  Top 0.305: U$14.P$10 64.45,55.6 64.77,55.92 80.96,55.92 83.5,53.38 P2.P$24
F2-500_E35
  Top 0.305: U$14.P$9 80.39,53.96 82.23,52.11 P2.P$26
F2-500_E36  (via drill 0.51)
  Top 0.305: v84.45,49.57 P2.P$30
  Bottom 0.254: CS.3 22.54,43.85 21.91,44.49 21.91,46.08 21.59,46.39 20,46.39 19.37,47.03 19.37,59.09 20,59.73
  Bottom 0.305: 20,59.73 34.61,59.73 39.69,54.65 78.42,54.65 83.5,49.57 v84.45,49.57
F2-500_N1  (via drill 0.51)
  Top 0.305: v99.38,63.54 P2.P$7 | U$13.P$9 v54.29,63.54
  Bottom 0.305: v54.29,63.54 v99.38,63.54
F2-500_N2  (via drill 0.51)
  Top 0.305: v99.38,62.27 P2.P$9 | U$13.P$10 v53.02,62.27
  Bottom 0.305: v53.02,62.27 v99.38,62.27
F2-500_N3  (via drill 0.51)
  Top 0.305: v99.38,61 P2.P$11 | U$13.P$11 v51.75,61
  Bottom 0.305: v51.75,61 v99.38,61
F2-500_N4  (via drill 0.51)
  Top 0.305: v99.38,59.73 P2.P$13 | U$13.P$12 v50.48,59.73
  Bottom 0.305: v50.48,59.73 v99.38,59.73
F2-500_N9  (via drill 0.51)
  Top 0.305: U$13.P$13 49.21,52.43 49.53,52.11 72.07,52.11 v80.01,44.17 | v99.38,54.65 P2.P$21
  Bottom 0.305: v80.01,44.17 84.77,44.17 95.25,54.65 v99.38,54.65
F2-500_N10  (via drill 0.51)
  Top 0.305: U$13.P$14 47.94,51.79 48.26,51.47 69.85,51.47 v77.15,44.17 | v99.38,52.11 P2.P$25
  Bottom 0.305: v77.15,44.17 79.38,41.95 86.36,41.95 96.52,52.11 v99.38,52.11
F2-500_N11  (via drill 0.51)
  Top 0.305: U$13.P$15 46.67,51.16 46.99,50.84 67.94,50.84 v77.15,41.63 | v99.38,50.84 P2.P$27
  Bottom 0.305: v77.15,41.63 78.74,40.04 87.31,40.04 98.11,50.84 v99.38,50.84
F2-500_N12  (via drill 0.51)
  Top 0.305: U$13.P$16 45.4,50.52 45.72,50.2 66.36,50.2 v77.15,39.41 | v99.38,49.57 P2.P$29
  Bottom 0.305: v77.15,39.41 78.11,38.46 88.27,38.46 v99.38,49.57
F2-500_N36
  Top 0.305: U$14.P$16 56.83,63.22 57.15,63.54 P2.P$8
F2-500_W15  (via drill 0.51)
  Top 0.305: v84.45,48.3 P2.P$32
  Bottom 0.254: SCLK.3 22.23,50.2 21.91,50.52 21.91,58.46
  Bottom 0.305: 21.91,58.46 22.54,59.09 33.66,59.09 39.05,53.7 70.8,53.7 76.2,48.3 v84.45,48.3
F2-500_W16  (via drill 0.51)
  Top 0.305: v84.45,47.03 P2.P$34
  Bottom 0.254: DIN.3 23.18,57.82 23.81,58.46
  Bottom 0.305: 23.81,58.46 32.7,58.46 38.73,52.43 66.99,52.43 72.39,47.03 v84.45,47.03
LD  (via drill 0.51)
  Top 0.254: v62.86,19.89 U$1.P$22
  Route15 0.254: v19.68,26.71 20,26.39 33.02,26.39 v33.34,26.07
  Bottom 0.254: v62.86,19.89 62.86,20.68 62.55,20.99 54.61,20.99 52.7,22.9 52.7,27.03 52.39,27.34 33.66,27.34 33.34,27.03 v33.34,26.07 | U$2.P$30 19.93,26.95 v19.68,26.71
MSS_GP_IO_0  (via drill 0.51)
  Top 0.305: U$6.P$6 48.26,19.41 48.58,19.72 48.58,24.17 43.5,29.25 43.5,57.19 45.09,58.78 v45.09,62.59
  Bottom 0.305: v45.09,62.59 9.21,62.59 8.89,62.9 U$9.7
MSS_GP_IO_1  (via drill 0.51)
  Top 0.305: U$6.P$7 47.62,20.04 47.94,20.36 47.94,23.85 42.86,28.93 42.86,58.14 43.81,59.09 v43.81,61.63
  Bottom 0.305: v43.81,61.63 8.26,61.63 7.62,62.27 7.62,69.25 U$9.8
MSS_GP_IO_2
  Top 0.305: RXTX.3 29.53,51.16 29.53,58.78 28.89,59.41 12.06,59.41 11.43,60.05 U$9.9
MSS_GP_IO_3  (via drill 0.51)
  Top 0.305: v45.72,32.42 44.13,33.69 44.13,55.6 46.35,57.82 v46.35,63.54 | U$21.P$4 54.31,33.08 54.61,33.38 v55.24,33.38
  Bottom 0.305: v45.72,32.42 54.93,32.42 55.24,32.74 v55.24,33.38 | v46.35,63.54 10.48,63.54 10.16,63.86 10.16,69.25 U$9.10
MSS_GP_IO_4
  Top 0.305: SHDN.3 30.8,59.41 30.16,60.05 14.61,60.05 13.97,60.68 U$9.11
N$1  (via drill 0.51)
  Top 0.254: 1_EN.2 28.26,13.06 26.99,14.33 26.99,18.77 26.67,19.09 26.67,36.23 v27.62,37.19
  Bottom 0.254: v27.62,37.19 29.53,37.19 29.56,37.15 29.56,35.95 U$2.P$1
N$2
  Bottom 0.254: U$2.P$24 28.22,24.45 27.94,24.17 27.94,16.87 4_EN.2
N$3  (via drill 0.51)
  Top 0.254: 3_EN.2 20.64,11.15 19.37,12.42 19.37,23.22 v19.68,23.53
  Bottom 0.254: U$2.P$25 20.6,24.45 v19.68,23.53
N$4  (via drill 0.51)
  Top 0.254: 2_EN.2 v20.64,37.19
  Bottom 0.254: v20.64,37.19 21.27,37.19 21.59,36.87 21.59,36.06 U$2.P$48
N$5
  Top 0.254: T1.P$4 55.5,11.09 56.85,12.44 U$1.P$4
N$6
  Top 0.254: U$1.P$5 57.35,12.31 57.15,12.1 57.15,11.79 57.47,11.47 57.47,10.21 57.15,9.9 T1.P$3 56.91,9.88
N$7  (via drill 0.51)
  Top 0.254: X1.P$1 13.6,43.9 13.97,43.54 13.97,24.49 14.29,24.17 v18.41,24.17
  Bottom 0.254: U$2.P$27 18.75,25.45 18.41,25.12 v18.41,24.17
N$8
  Top 0.254: U$1.P$9 59.35,13.87 60.71,12.52 60.8,12.42 C4.1
N$9
  Top 0.35: T1.P$1 56.82,8.6 52.7,4.48 U$3.SIGNAL
N$10
  Top 0.254: U$1.P$10 59.85,14 61.78,12.07 61.78,11.91 C5.1 62.1,11.91
N$11
  Top 0.254: C4.2 60.8,9.29 T2.P$4
N$12
  Top 0.254: C5.2 61.94,9.48 T2.P$3
N$13  (via drill 0.51)
  Top 0.254: RX/TX.2 20.64,4.8 21.91,6.07 v21.91,23.22
  Bottom 0.254: v21.91,23.22 22.23,23.22 23.18,24.17 23.18,26.07 22.8,26.45 U$2.P$29
N$14  (via drill 0.51)
  Top 0.254: 66.37,22.25 R1.1 67.63,21.95 v67.94,22.26 | C17.2 55.56,24.8 v56.2,24.17 56.2,23.85 57.35,22.7 U$1.P$32
  Bottom 0.254: v67.94,22.26 56.52,22.26 56.2,22.58 v56.2,24.17
N$15
  Top 0.35: T2.P$1 62.24,7.96 64.77,5.44 U$4.SIGNAL
N$16
  Top 0.254: C19.1 R2.1 R1.2 | U$1.P$24 62.12,20.89 62.71,21.47 64.75,21.47 R1.2 | R1.2 65.07,21.93
N$17
  Top 0.254: R2.2 68.12,20.8 C18.2
N$18
  Top 0.254: U$1.P$28 59.35,24.47 60.28,25.39 C20.2 60.26,25.77 C22.1
N$19
  Top 0.254: U$1.P$29 58.85,25.63 C20.1 58.98,26.87 C21.1
N$20
  Top 0.508: C22.2 60.28,28.3 61.28,28.3 64.77,24.8 65.18,24.8 U$5.HOT
N$21
  Top 0.254: U$1.P$33 56.83,21.53 56.83,22.42 54.29,24.96 C23.1
N$22
  Top 0.305: U$6.P$1 45.52,15.38 C24.2
N$23
  Bottom 0.254: X1.P$16 7.17,37 6.99,37.19 6.99,44.81 7.3,45.12 13.97,45.12 14.29,44.81 14.29,40.04 14.61,39.73 18.1,39.73 18.41,39.41 18.41,31.47 18.93,30.95 U$2.P$38
N$24
  Top 0.305: U$6.P$25 39.05,18.14 38.73,17.82 38.73,14.96 38.42,14.64 C30.1
N$25  (via drill 0.51)
  Route15 0.254: CS.1 17.46,43.85 17.14,43.54 17.14,30.2 17.46,29.88 34.92,29.88 v35.24,29.57
  Bottom 0.254: U$2.P$13 34.86,29.95 v35.24,29.57
N$26  (via drill 0.51)
  Route15 0.254: SCLK.1 16.83,50.2 16.51,49.89 16.51,29.57 16.83,29.25 32.18,29.25 32.38,29.45 33.45,29.45 v34.29,28.61
  Bottom 0.254: U$2.P$14 33.45,29.45 v34.29,28.61
N$27
  Top 0.305: U$6.P$28 40.21,15.38 C25.2
N$28  (via drill 0.41, 0.51)
  Route15 0.254: v16.19,51.47 15.88,51.16 15.88,28.93 16.19,28.61 v33.02,28.61
  Bottom 0.254: U$2.P$16 32.86,28.45 v33.02,28.61 | DIN.1 15.88,56.55 15.56,56.24 15.56,52.11 v16.19,51.47
N$29  (via drill 0.51)
  Top 0.254: SHDN.1 25.72,55.28 24.45,54.01 24.45,38.46 24.77,38.14 28.26,38.14 28.57,37.82 28.57,21.95 28.89,21.63 31.11,21.63 v31.43,21.95
  Bottom 0.254: U$2.P$22 29.83,25.45 30.16,25.12 30.16,22.58 30.8,21.95 v31.43,21.95
N$30  (via drill 0.51)
  Top 0.254: RXTX.1 25.72,39.09 26.04,38.77 28.57,38.77 29.21,38.14 29.21,23.22 29.53,22.9 v32.38,22.9
  Bottom 0.254: U$2.P$20 32.01,26.45 32.38,26.07 v32.38,22.9
N$32  (via drill 0.51)
  Top 0.254: X1.P$2 12.87,41.14 13.34,40.68 13.34,23.85 13.97,23.22 v17.46,23.22
  Bottom 0.254: v17.46,23.22 17.46,28.93 17.98,29.45 U$2.P$35
N$33
  Bottom 0.254: X1.P$3 16.58,38.38 17.14,37.82 17.14,30.52 17.78,29.88 17.85,29.95 U$2.P$36
N$34
  Bottom 0.254: X1.P$4 16.17,35.62 16.51,35.28 16.51,22.58 16.83,22.26 23.5,22.26 23.81,22.58 23.81,27.98 23.34,28.45 U$2.P$33
N$35
  Bottom 0.254: X1.P$5 15.44,32.86 15.88,32.42 15.88,21.95 16.19,21.63 23.97,21.63 24.29,21.95 24.29,31.79 24.13,31.95 U$2.P$40
N$36
  Bottom 0.254: U$2.P$43 24.37,33.45 24.77,33.06 24.77,21.31 24.45,20.99 15.56,20.99 15.24,21.31 15.24,29.88 15.02,30.1 X1.P$6
N$37
  Bottom 0.254: X1.P$7 14.29,27.34 14.61,27.03 14.61,20.68 14.92,20.36 24.92,20.36 25.24,20.68 25.24,33.69 24.98,33.95 U$2.P$44
N$38
  Bottom 0.254: U$2.P$46 25.41,34.95 25.72,34.65 25.72,20.04 25.4,19.72 14.29,19.72 13.97,20.04 13.97,24.17 13.55,24.58 X1.P$8
N$39
  Bottom 0.254: X1.P$9 13.14,21.82 13.34,21.63 13.34,19.41 13.65,19.09 25.88,19.09 26.19,19.41 26.19,34.8 25.55,35.45 U$2.P$47
N$40
  Bottom 0.254: X1.P$14 13.39,42.52 13.65,42.27 13.65,39.41 13.97,39.09 17.46,39.09 17.78,38.77 17.78,30.84 18.16,30.45 U$2.P$37
N$41  (via drill 0.51)
  Route15 0.254: v32.07,27.66 34.61,27.66 34.92,27.98 36.83,27.98 37.47,27.34 37.47,24.8 36.83,24.17 32.7,24.17 32.38,24.49 23.18,24.49 22.86,24.17 22.86,22.9 22.23,22.26 13.34,22.26 12.38,23.22 10.48,23.22 9.84,23.85 9.84,38.34 X1.P$15
  Bottom 0.254: U$2.P$19 31.36,26.95 v32.07,27.66
N$42
  Top 0.305: U$21.P$5 54.81,30.95 54.93,30.84 55.24,30.84 | 55.24,30.84 55.56,30.84 55.81,31.09 U$21.P$7 | U$21.P$6 55.31,30.9 55.24,30.84
N$43
  Top 0.254: U$14.P$1 56.83,45.76 59.69,42.9 59.69,38.69 U$21.P$24
N$44
  Top 0.254: U$14.P$2 58.1,45.44 61.28,42.27 61.28,38.46 60.96,38.14 60.93,38.17 U$21.P$23
N$45
  Top 0.254: U$14.P$3 59.37,45.12 61.91,42.58 61.91,38.14 61.44,37.67 U$21.P$22
N$46
  Top 0.254: U$14.P$4 60.64,44.81 62.55,42.9 62.55,37.82 61.89,37.17 U$21.P$21
N$47
  Top 0.254: U$14.P$5 61.91,44.49 63.18,43.22 63.18,37.19 62.66,36.67 U$21.P$20
N$48
  Top 0.254: U$14.P$6 63.18,44.17 63.82,43.54 63.82,36.55 63.43,36.17 U$21.P$19
N$49
  Top 0.254: U$14.P$7 64.45,35.92 64.2,35.67 U$21.P$18
N$50
  Top 0.254: U$14.P$8 65.72,35.6 65.29,35.17 U$21.P$17
N$51
  Top 0.254: U$13.P$8 54.29,45.76 51.44,42.9 51.44,38.69 U$21.P$37
N$52
  Top 0.254: U$13.P$7 53.02,45.44 49.85,42.27 49.85,38.46 50.14,38.17 U$21.P$38
N$53
  Top 0.254: U$13.P$6 51.75,45.12 49.21,42.58 49.21,38.14 49.69,37.67 U$21.P$39
N$54
  Top 0.254: U$13.P$5 50.48,44.81 48.58,42.9 48.58,37.5 48.91,37.17 U$21.P$40
N$55
  Top 0.254: U$13.P$4 49.21,44.49 47.94,43.22 47.94,37.19 48.46,36.67 U$21.P$41
N$56
  Top 0.254: U$13.P$3 47.94,44.17 47.31,43.54 47.31,36.55 47.69,36.17 U$21.P$42
N$57
  Top 0.254: U$13.P$2 46.67,36.23 47.24,35.67 U$21.P$43
N$58
  Top 0.254: U$13.P$1 45.4,35.6 45.84,35.17 U$21.P$44
N$59
  Bottom 0.254: X1.P$17 6.75,34.24 6.35,34.65 6.35,45.44 6.67,45.76 14.61,45.76 14.92,45.44 14.92,40.68 15.24,40.36 18.73,40.36 19.05,40.04 19.05,32.8 19.39,32.45 U$2.P$41
RX_I+  (via drill 0.51)
  Top 0.254: v51.28,29.09 51.28,23.06 53.95,20.39 U$1.P$38 | U$21.P$11 57.81,29.91 56.99,29.09 v56.36,29.09
  Bottom 0.254: v51.28,29.09 v56.36,29.09
RX_I-  (via drill 0.51)
  Top 0.254: U$1.P$37 54.08,20.89 52.07,22.9 52.07,23.53 52.39,23.85 52.39,24.17 52.07,24.49 52.07,24.8 52.39,25.12 52.39,25.44 52.07,25.76 52.07,26.07 52.39,26.39 52.39,26.71 52.07,27.03 52.07,27.34 52.39,27.66 52.39,27.98 52.07,28.3 52.07,28.61 52.39,28.93 v52.39,29.88 | U$21.P$10 57.31,30.05 57.15,29.88 56.83,29.88 56.52,30.2 56.2,30.2 55.56,29.57 54.93,29.57 v54.61,29.88
  Bottom 0.254: v52.39,29.88 52.39,30.04 52.7,30.36 54.29,30.36 54.61,30.04 v54.61,29.88
RX_Q+
  Top 0.254: U$21.P$2 53.31,29.22 53.02,28.93 53.02,22.58 53.98,21.63 55.28,21.63 U$1.P$36
RX_Q-
  Top 0.254: U$1.P$35 55.88,21.54 55.88,22.1 55.72,22.26 54.61,22.26 53.53,23.34 53.53,28.8 53.81,29.09 U$21.P$3
RXHP  (via drill 0.51)
  Top 0.254: v34.29,20.99 34.29,23.85 33.66,24.49 30.8,24.49 30.48,24.8 30.48,34.33 30.8,34.65 v35.56,34.65 | U$1.P$40 52.73,19.39 v52.39,19.72
  Bottom 0.254: U$2.P$12 35.49,30.45 35.56,30.52 v35.56,34.65 | v52.39,19.72 52.07,20.04 35.56,20.04 34.61,20.99 v34.29,20.99
RXTX  (via drill 0.51)
  Top 0.254: v53.98,14.01 54.29,14.01 54.61,14.33 54.61,15.32 U$1.P$48
  Bottom 0.254: RXTX.2 28.26,45.6 28.57,45.28 33.5,45.28 35.56,47.35 56.52,47.35 | 71.75,32.11 71.75,17.18 71.44,16.87 54.93,16.87 54.29,16.23 54.29,14.48 v53.98,14.01
  Bottom 0.305: 56.52,47.35 57.47,47.35 71.75,33.06 71.75,32.11
SCLK  (via drill 0.51)
  Top 0.254: U$1.P$18 62.8,17.89 v63.02,17.66
  Route15 0.254: v35.88,26.07 35.88,25.44 35.72,25.28 32.86,25.28 32.7,25.44 15.56,25.44 15.24,25.76 15.24,52.11 15.56,52.43 20.32,52.43 20.64,52.11 SCLK.2
  Bottom 0.254: v35.88,26.07 36.2,26.39 51.12,26.39 51.44,26.07 51.44,22.26 53.98,19.72 60.96,19.72 62.55,18.14 v63.02,17.66
SHDN_B  (via drill 0.51)
  Top 0.254: U$1.P$12 61.84,14.71 63.18,13.37 63.18,12.26 v63.34,12.1
  Bottom 0.254: 73.66,34.01 73.66,12.1 73.34,11.79 63.82,11.79 63.5,12.1 v63.34,12.1 | 58.42,49.25 37.78,49.25 36.83,50.2 32.7,50.2 32.38,50.52 32.38,52.11 32.07,52.43 28.57,52.43 28.26,52.74 SHDN.2
  Bottom 0.305: 58.42,49.25 62.87,49.25 73.66,38.46 73.66,34.01
TX_I+
  Top 0.254: 45.54,16.89 U$6.P$2 46.67,16.87 46.99,16.55 46.99,13.69 47.62,13.06 48.9,13.06 49.53,13.69 49.53,16.55 49.87,16.89 U$1.P$45
TX_I-
  Top 0.254: U$1.P$44 49.41,17.39 48.9,16.87 48.9,14.01 48.58,13.69 47.94,13.69 47.62,14.01 47.62,17.02 47.15,17.5 U$6.P$3
TX_Q+  (via drill 0.51)
  Top 0.254: U$1.P$43 50.1,17.89 v49.85,18.14 | v42.55,18.14 42.55,17.18 42.23,16.87 41.59,16.87
  Top 0.305: U$6.P$27 41.59,16.87
  Bottom 0.254: v42.55,18.14 v49.85,18.14
TX_Q-  (via drill 0.51)
  Top 0.254: U$1.P$42 51.5,18.39 v50.48,19.09
  Top 0.305: v43.18,19.09 42.23,19.09 41.59,18.45 41.59,17.82 41.27,17.5 U$6.P$26
  Bottom 0.254: v43.18,19.09 v50.48,19.09
VDD3.3  (3 unrouted)
VDD5  (3 unrouted)
VIN
  Top 0.508: C74.1 92.08,12.74 92.39,12.42 92.39,11.47 | 92.39,11.47 U2.P$3 | U2.P$1 92.39,9.57 92.39,9.56 92.39,11.47 | C75.1 92.08,19.09 92.39,19.41 92.39,20.36 | 92.39,20.36 U1.P$1 | U1.P$3 92.39,22.26 92.39,20.36
  Top 0.762: 91.44,9.23 U2.P$1
  Top 1.27: VIN.3 91.44,9.23 | 92.08,19.09 92.08,13.16 C74.1
  pour Top: 84.77,6.71 84.45,6.39 84.45,0.67 84.77,0.36 92.39,0.36 92.71,0.67 92.71,6.39 92.39,6.71

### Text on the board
tPlace: RF & SPI: | ----------------- | DAC: | RX/TX -> MSS_GPIO_2(W1) | ----------------- | D0 -> F2-200-IO_0 (E3) | SHDN -> MSS_GPIO_4(AA1) | D1 -> F2-200-IO_1 (F3) | D2 -> F2-200-IO_2 (G4) | DIN -> F2-500_W16 (K6) | D3 -> F2-200-IO_3 (H5) | CS -> F2-500_E36(F17) | D4 -> F2-200-IO_4 (H6) | RF front-end | D5 -> F2-200-IO_5 (J6) | SCLK -> F2-500_W15 (L6) | Kuo, 07/12 '11 | D6 -> F2-200-IO_6(B22) | D7 -> F2-200-IO_7(C22) | Rev: 01 | DACEN -> MSS_GPIO_0 (V1) | CLK -> F2-200-IO_8 (F1) | ADC: | PD -> MSS_GPIO_1 (R3) | ----------------- | D0_A -> F2-500_N1 (D7) | D1_A -> F2-500_N2 (E8) | D2_A -> F2-500_N3 (C4) | D3_A -> F2-500_N4 (C5) | D4_A -> F2-500_N9 (D8) | D5_A -> F2-500_N10(C7) | D6_A -> F2-500_N11(C8) | D7_A -> F2-500_N12(B7) | D0_B -> F2-500_N36(A18) | D1_B -> F2-500_E11(K17) | D2_B -> F2-500_E12(J17) | D3_B -> F2-500_E23(F21) | D4_B -> F2-500_E24(F20) | D5_B -> F2-500_E33(G18) | D6_B -> F2-500_E34(G17) | D7_B -> F2-500_E35(E18) | DFS -> MSS_GPIO_3 (Y1)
